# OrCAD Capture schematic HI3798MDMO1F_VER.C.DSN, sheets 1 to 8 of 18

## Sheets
1 SHEET_18: size A3
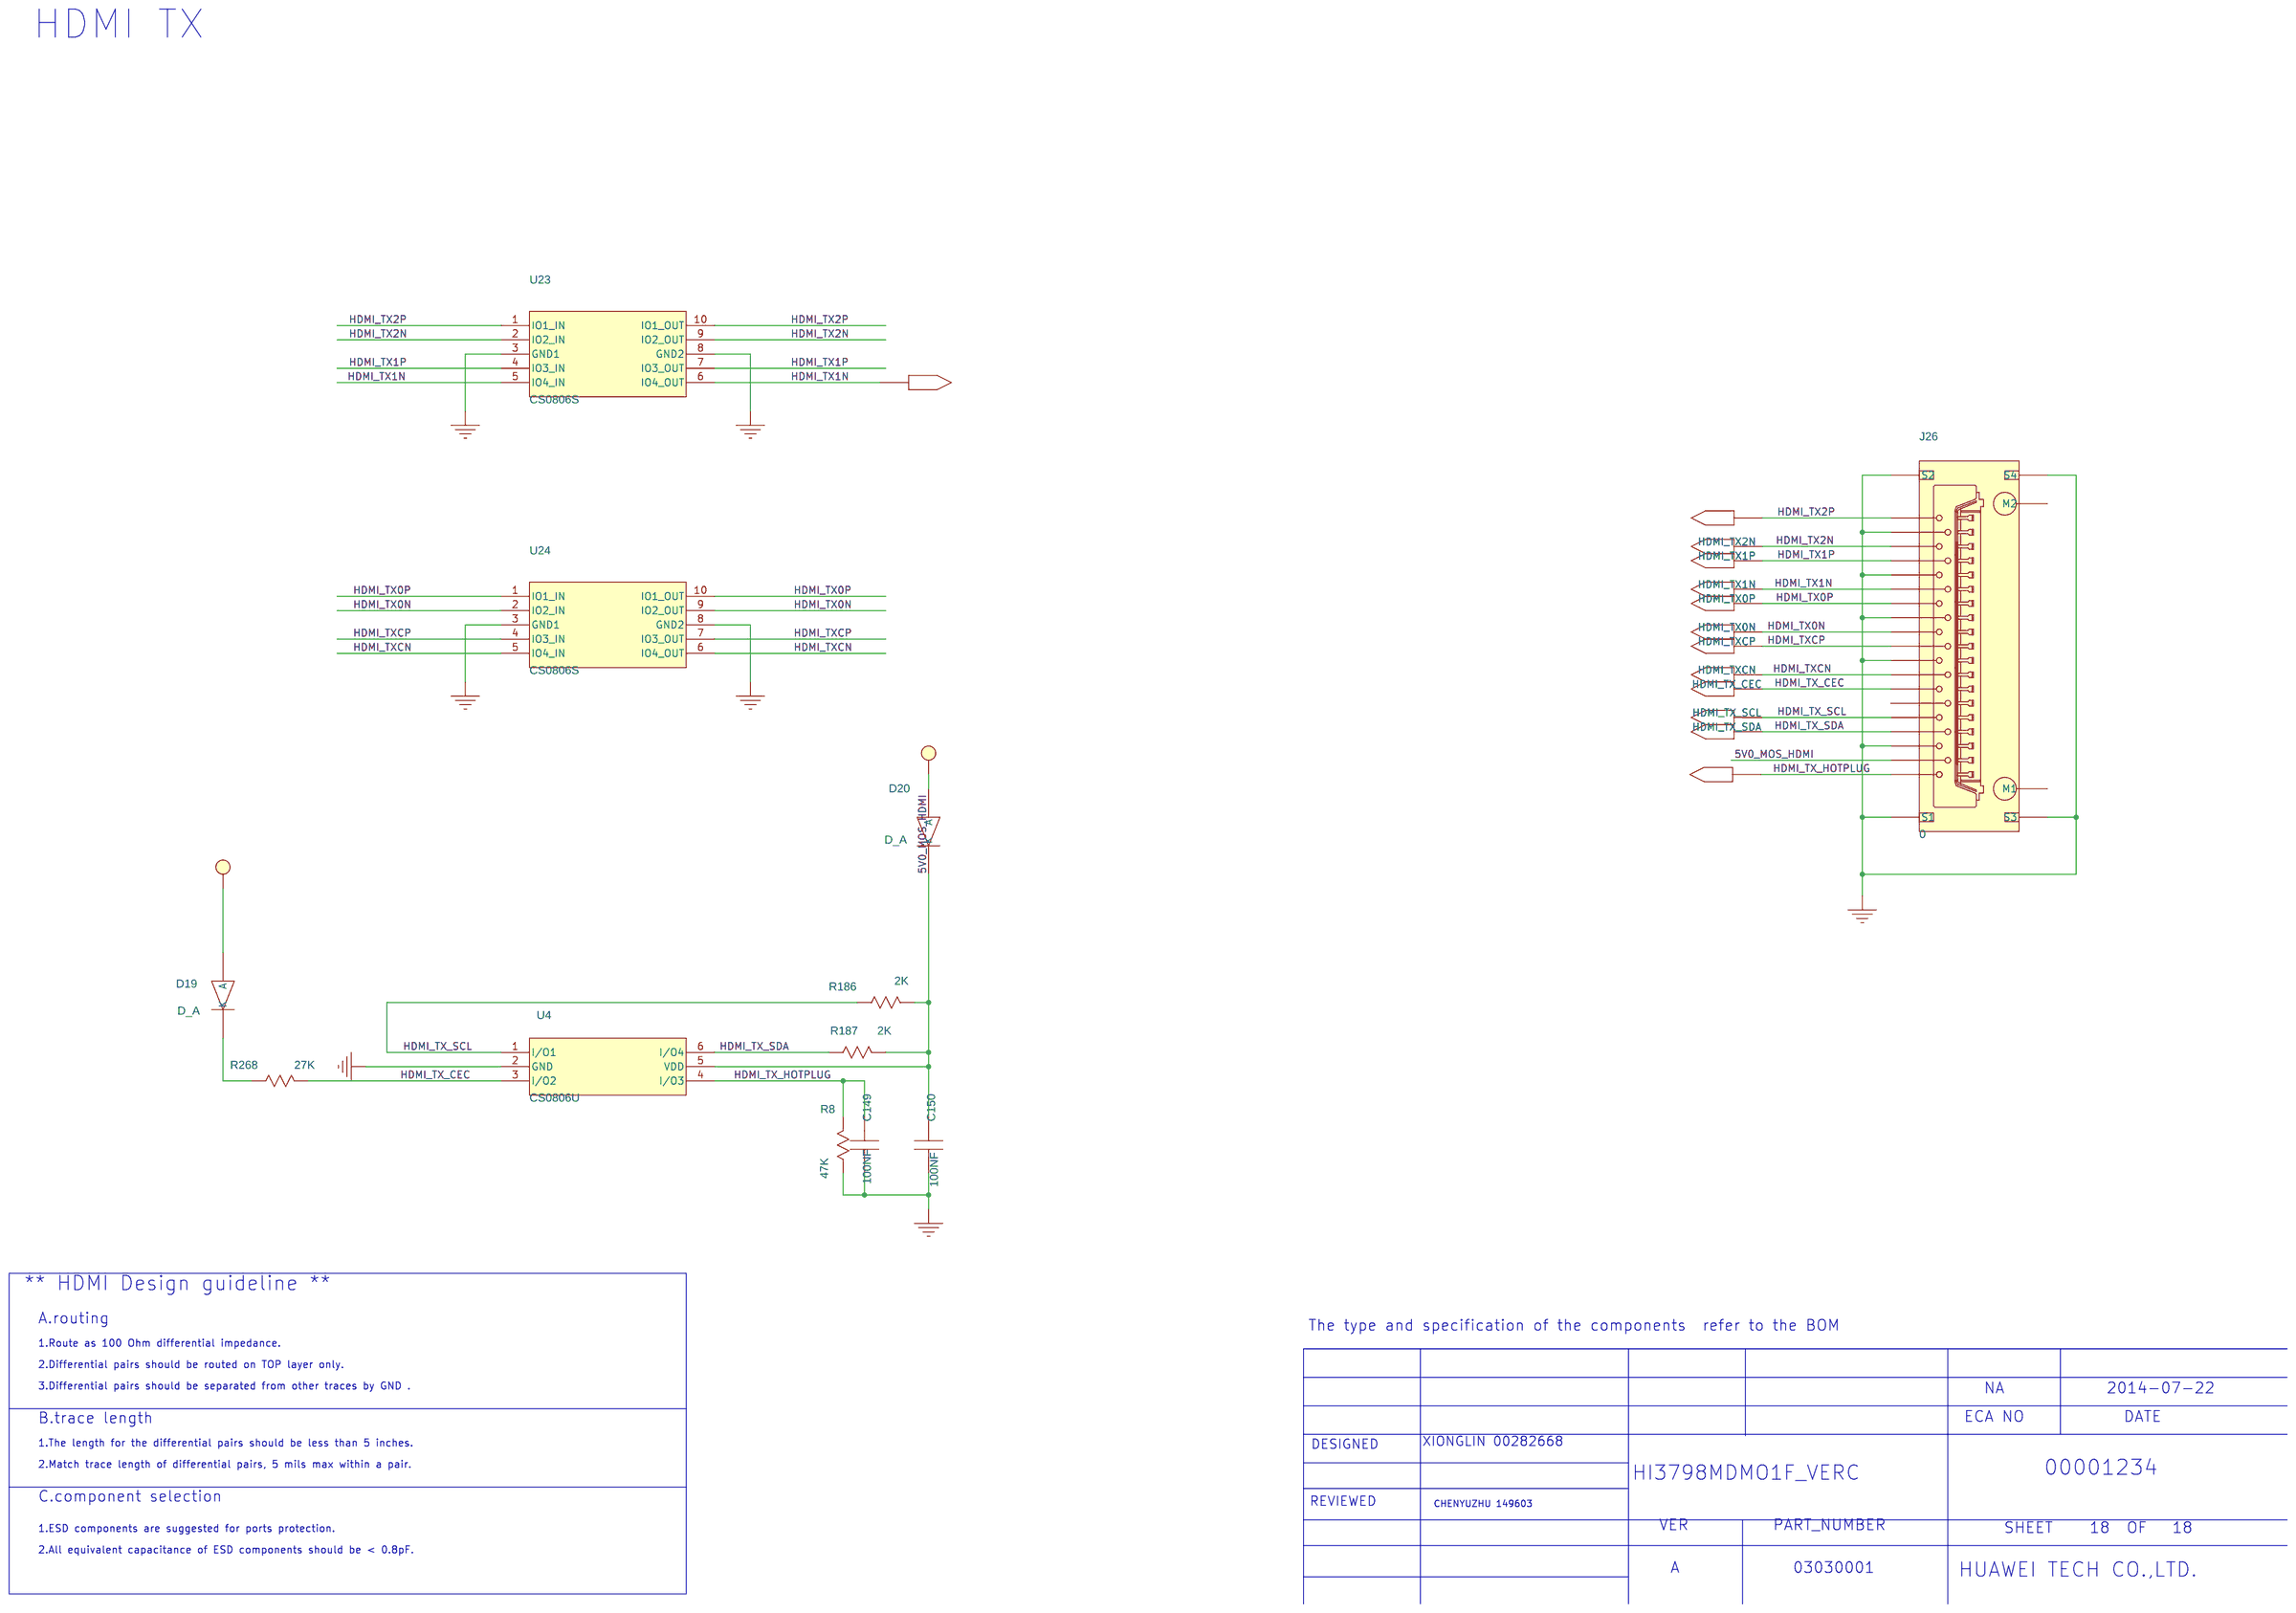
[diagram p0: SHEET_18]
2 SHEET_17: size A3
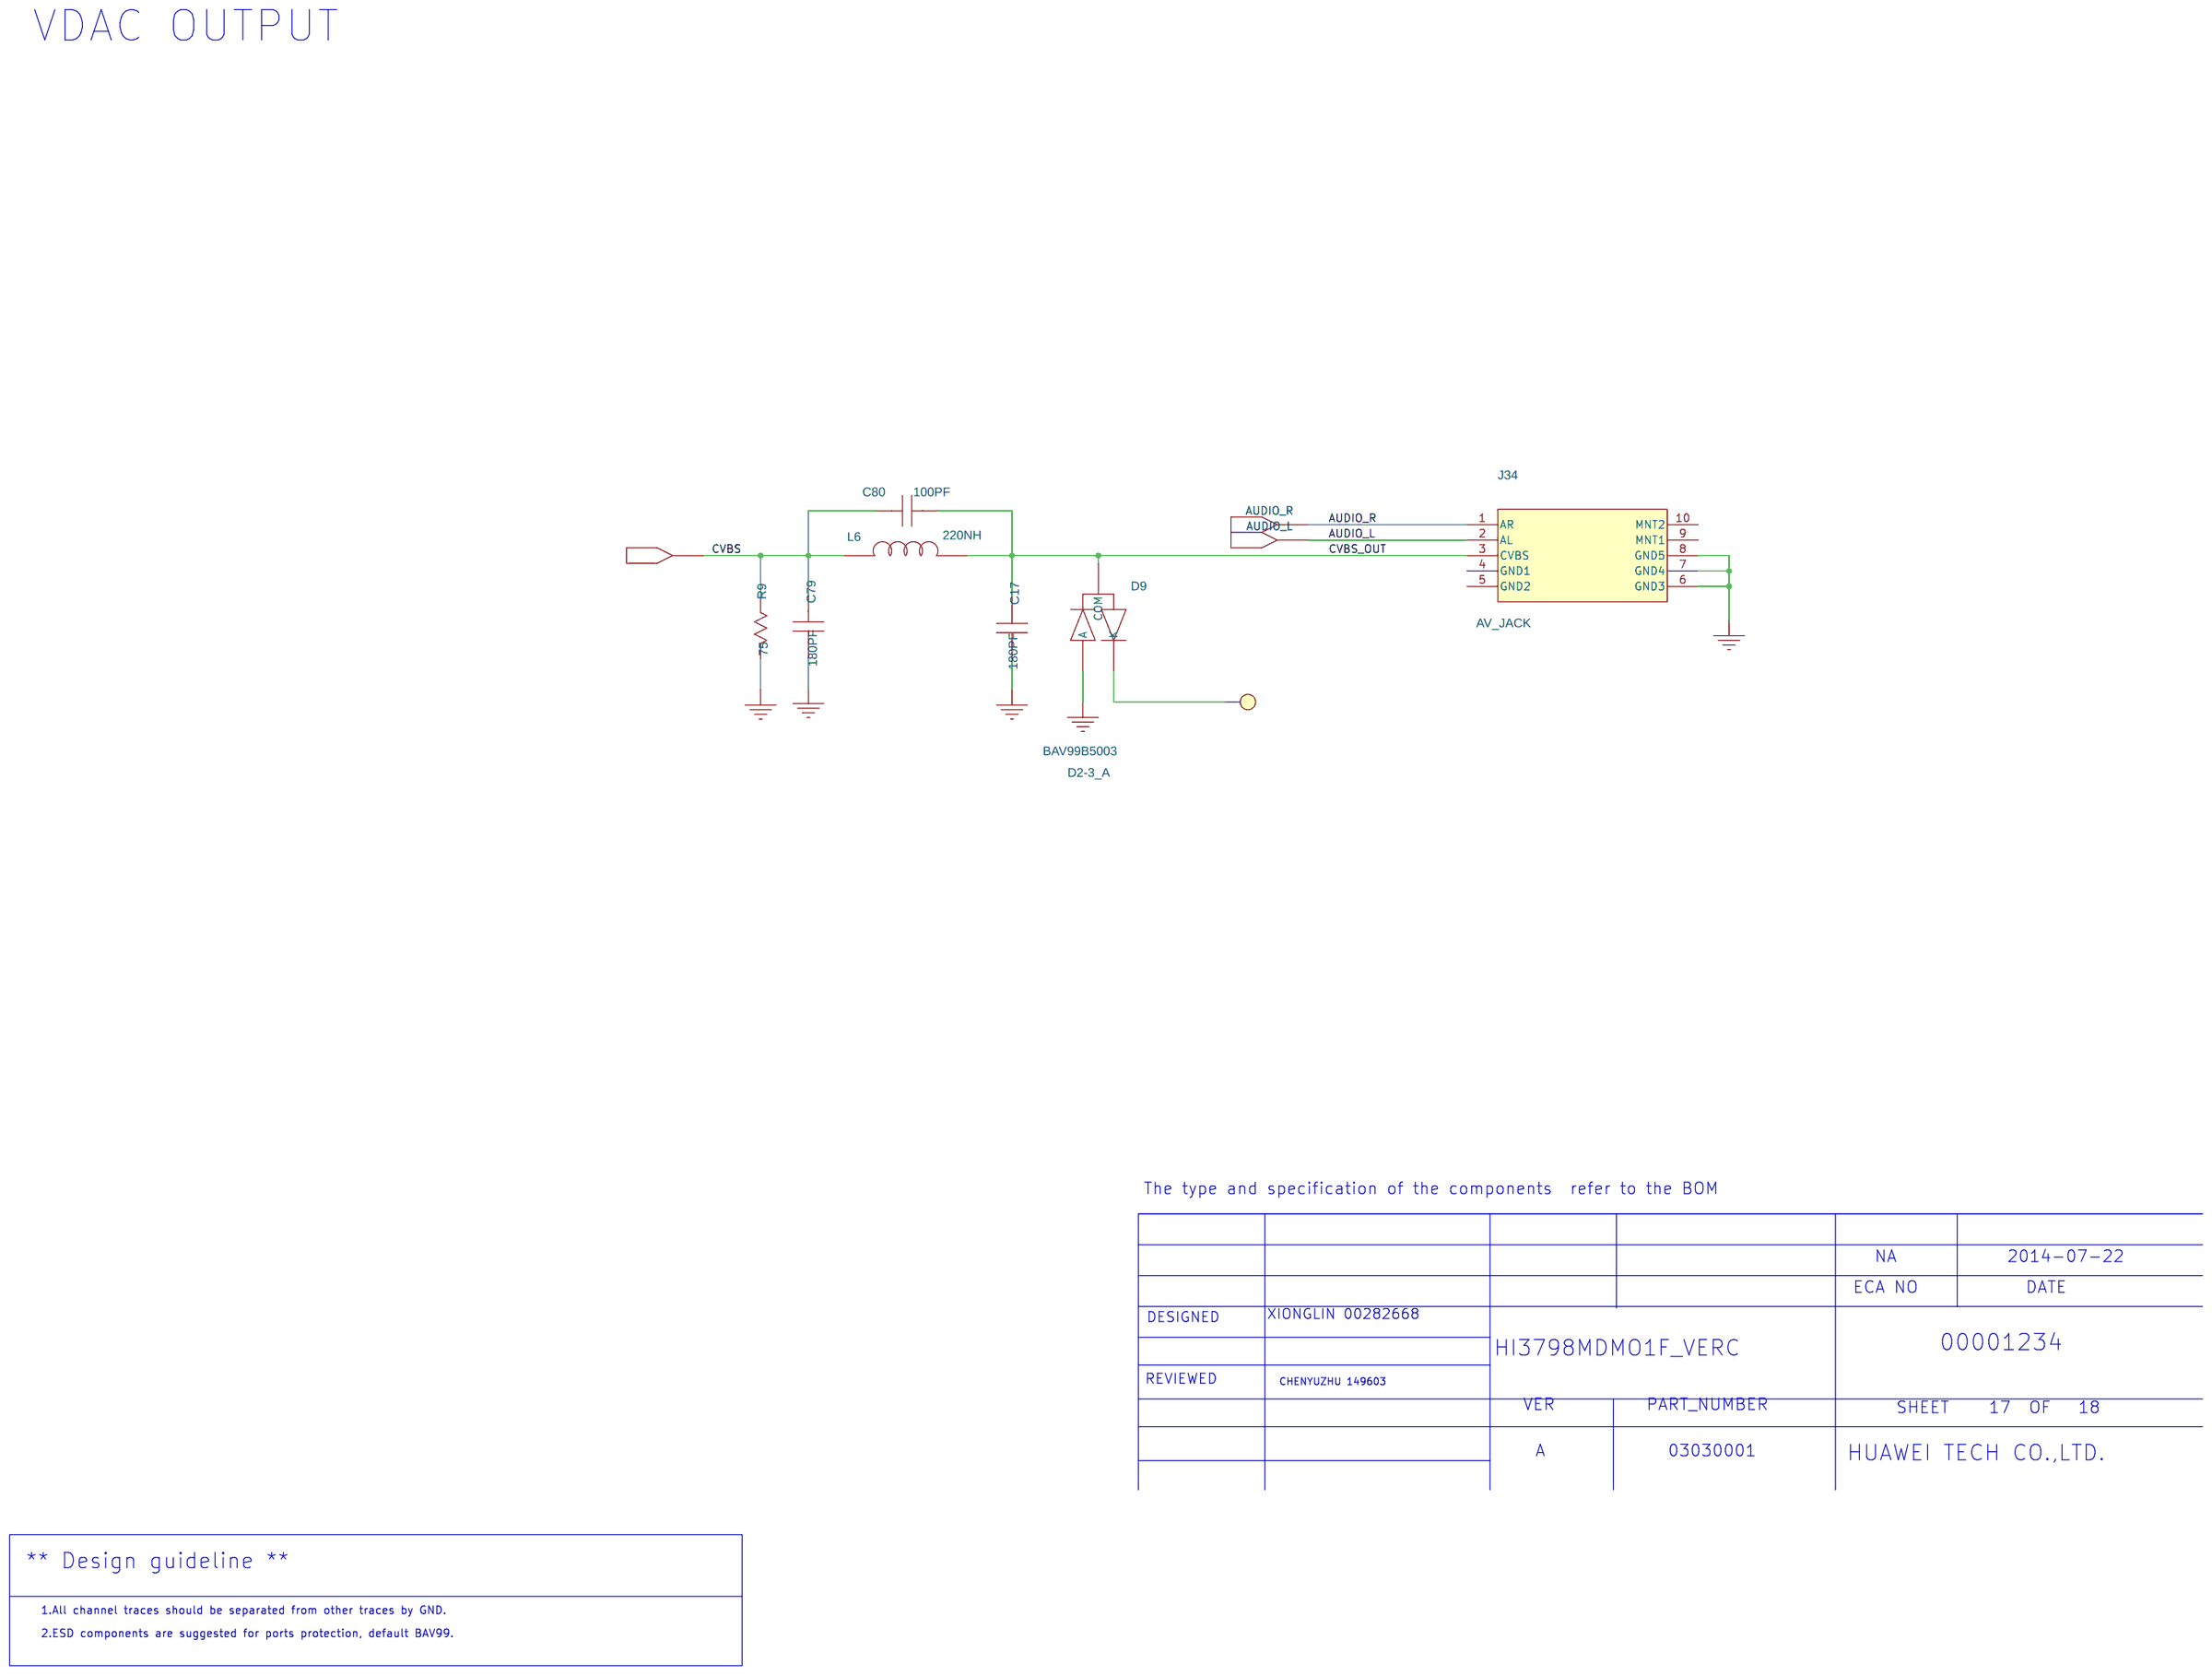
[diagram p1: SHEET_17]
3 SHEET_16: size A3
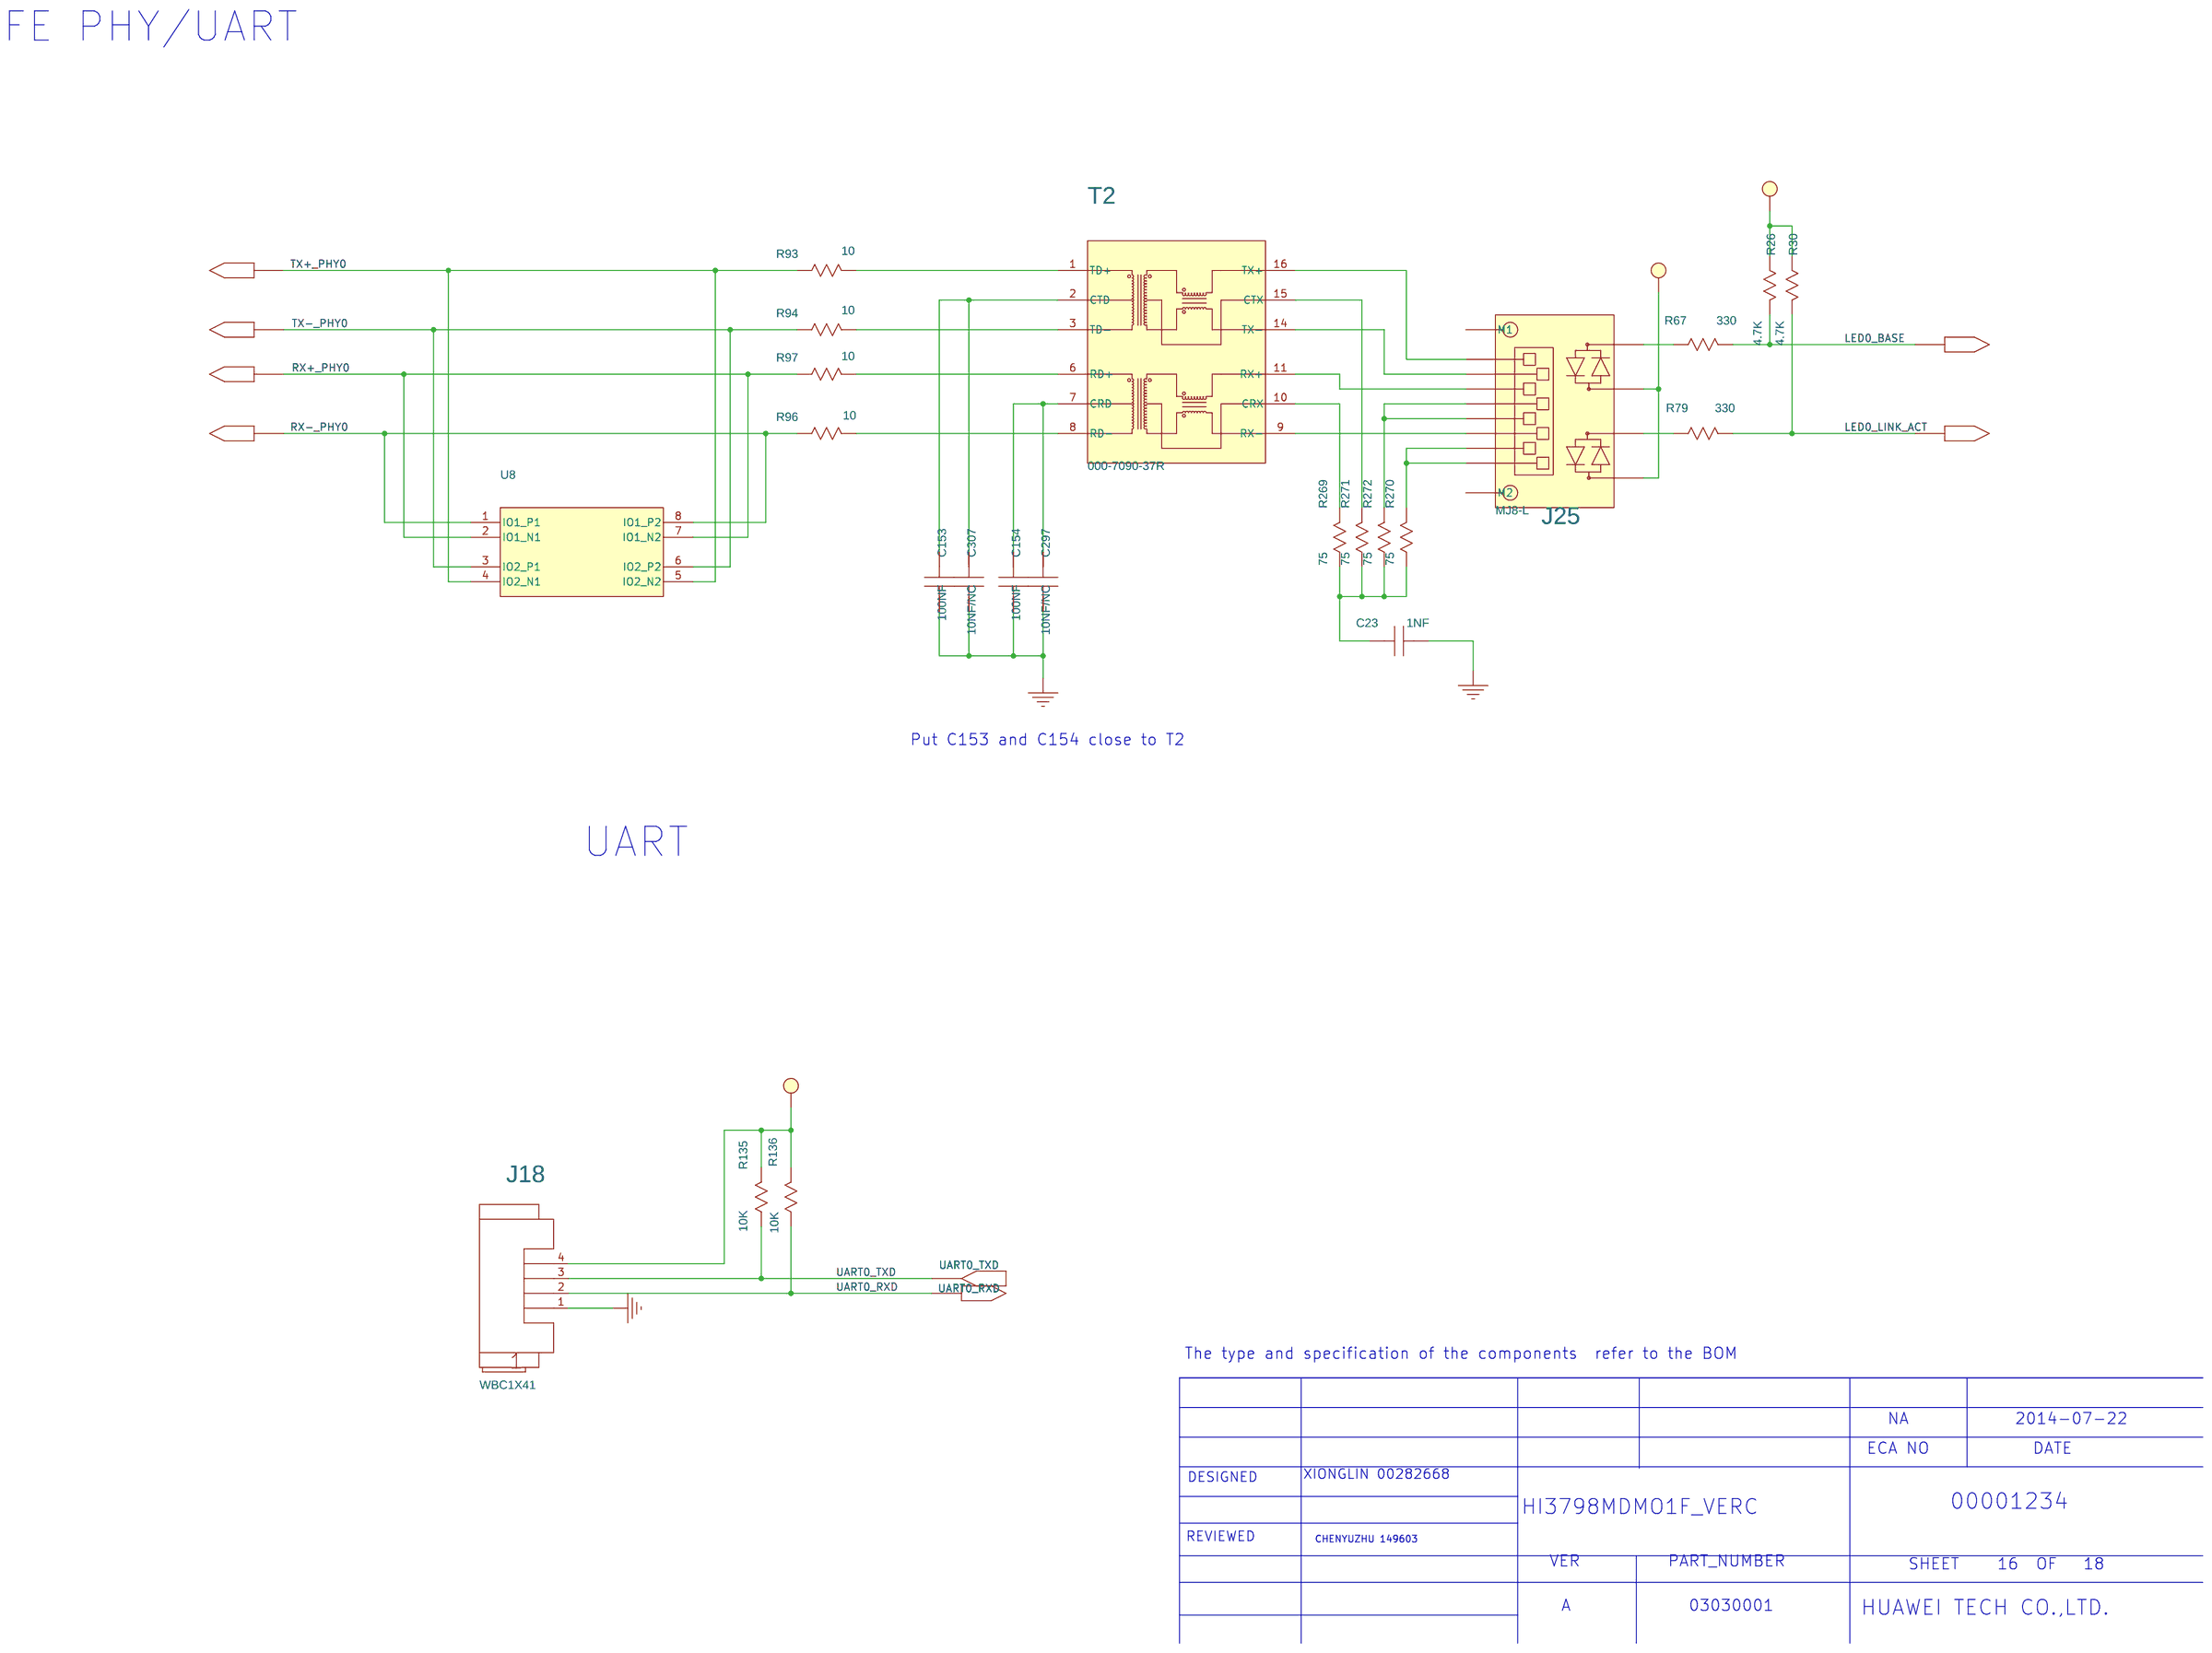
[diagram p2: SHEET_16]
4 SHEET_15: size A3
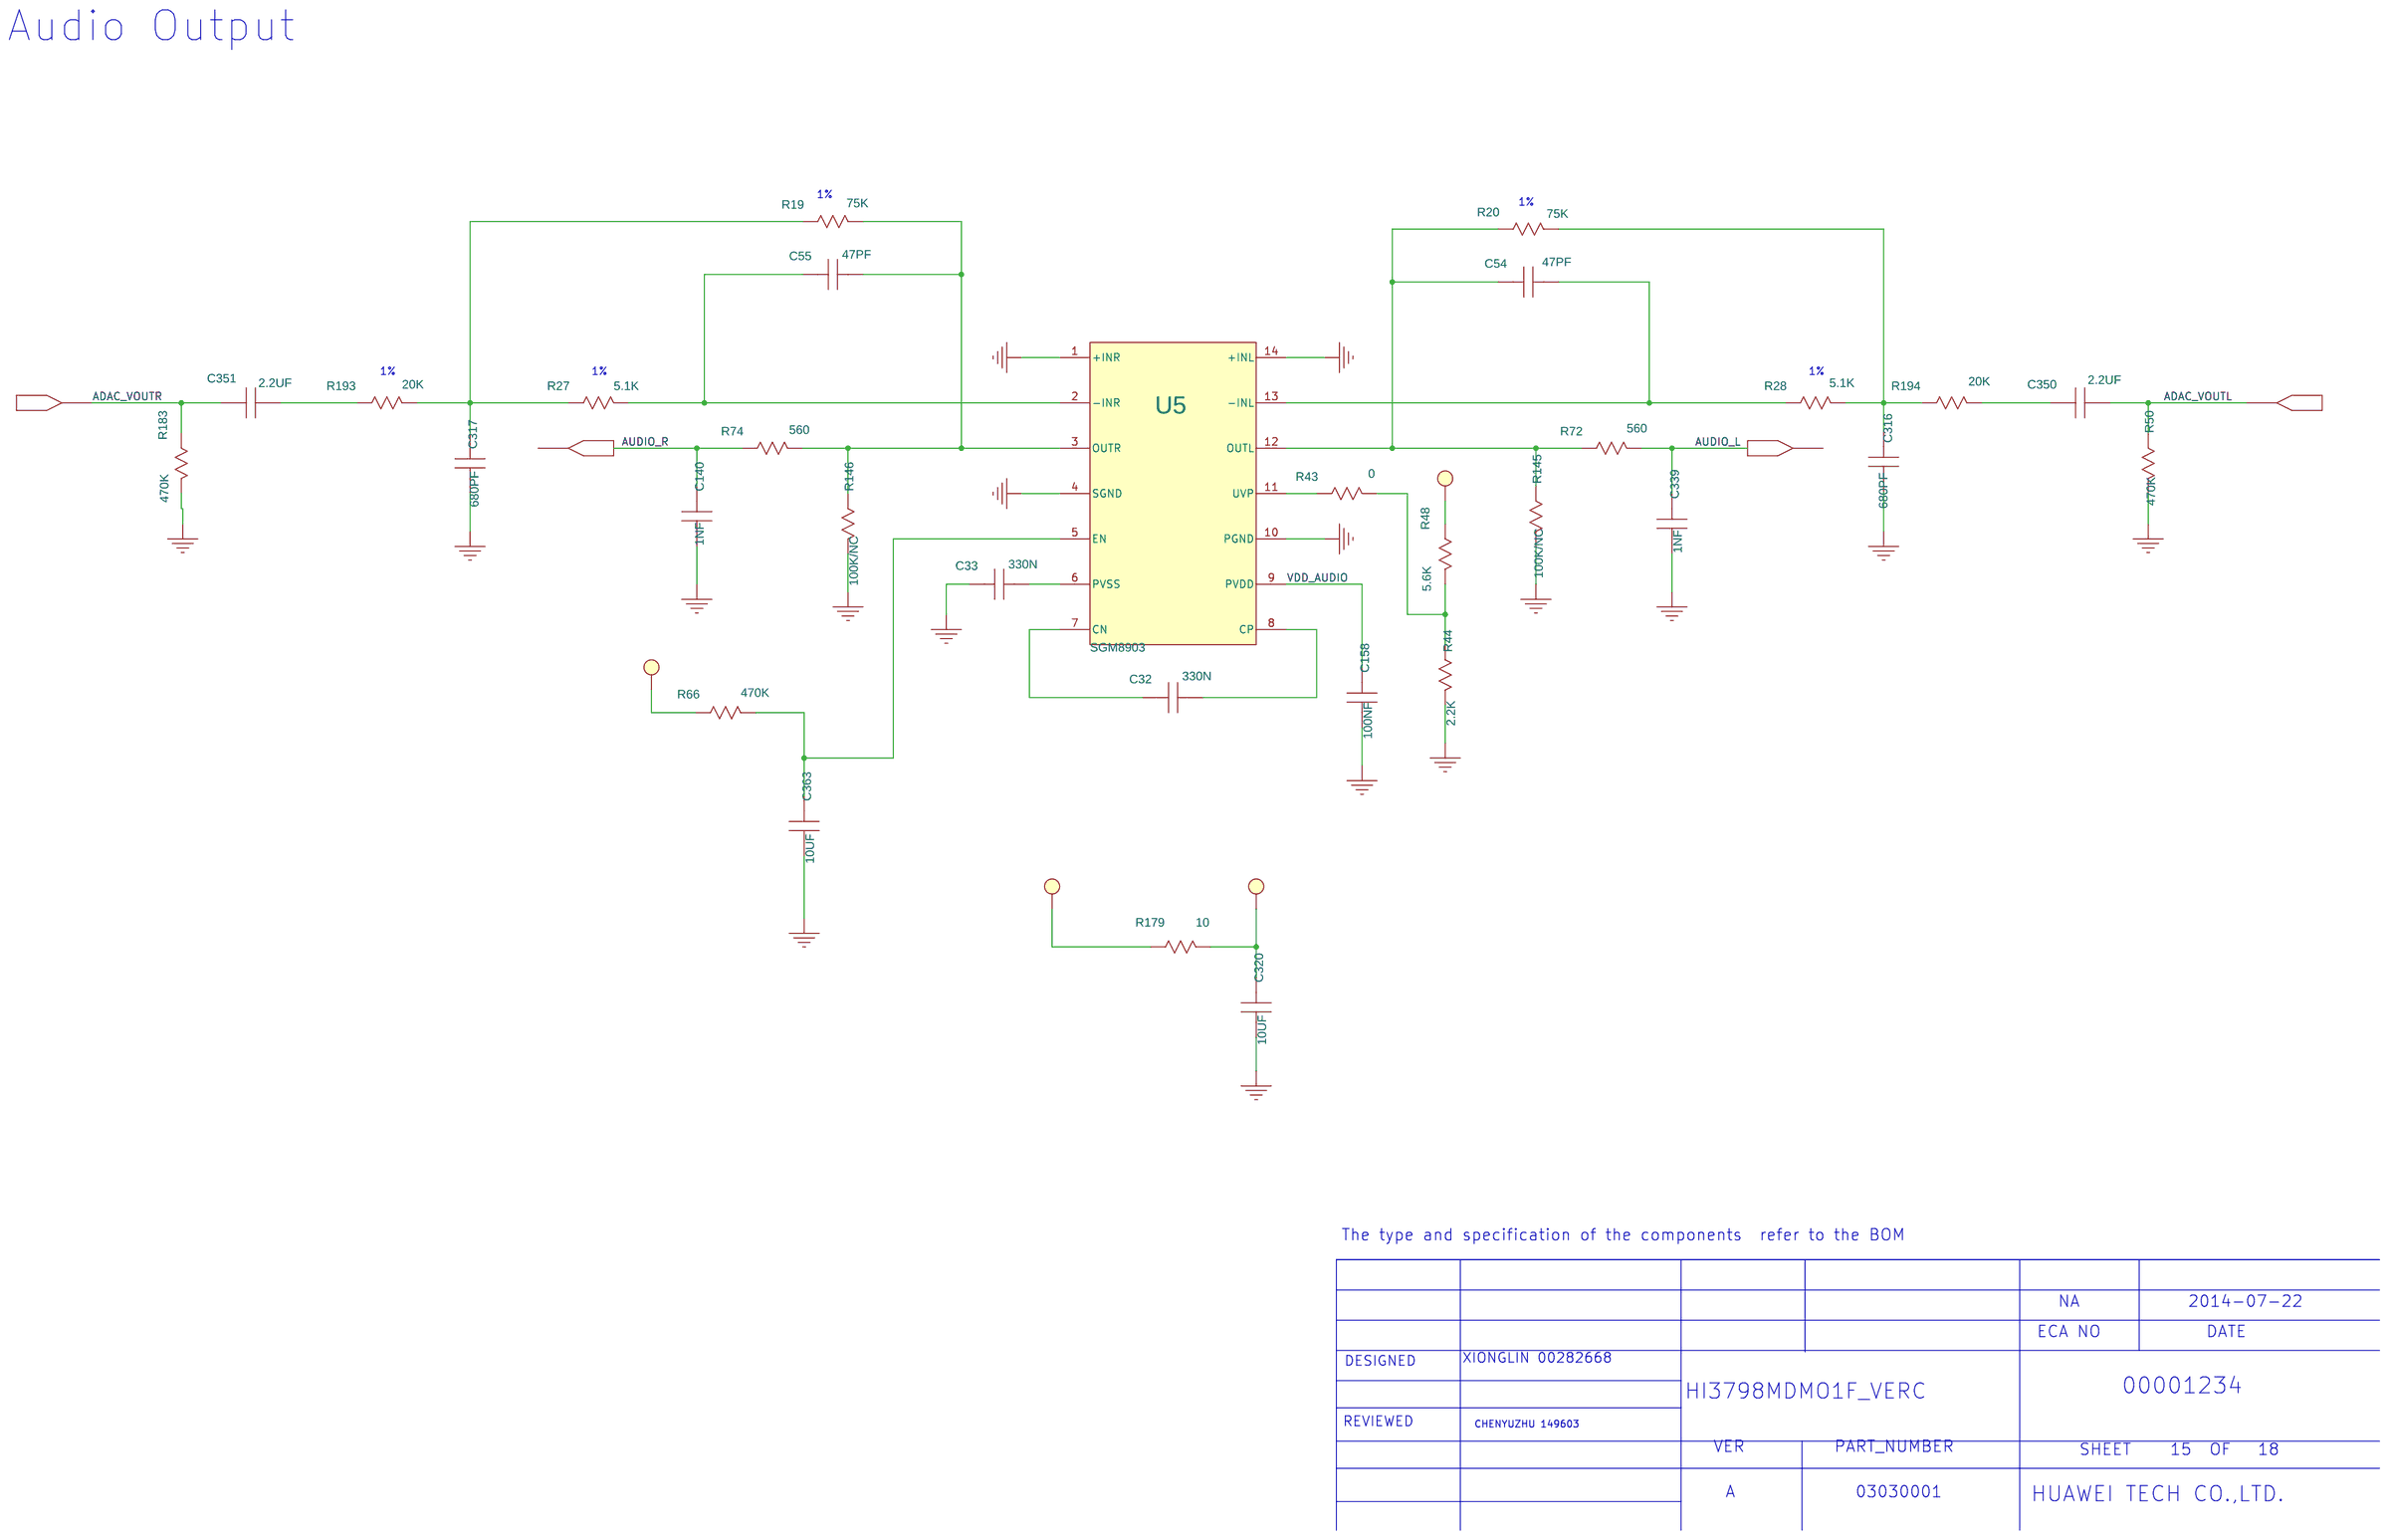
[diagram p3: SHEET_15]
5 SHEET_14: size A3
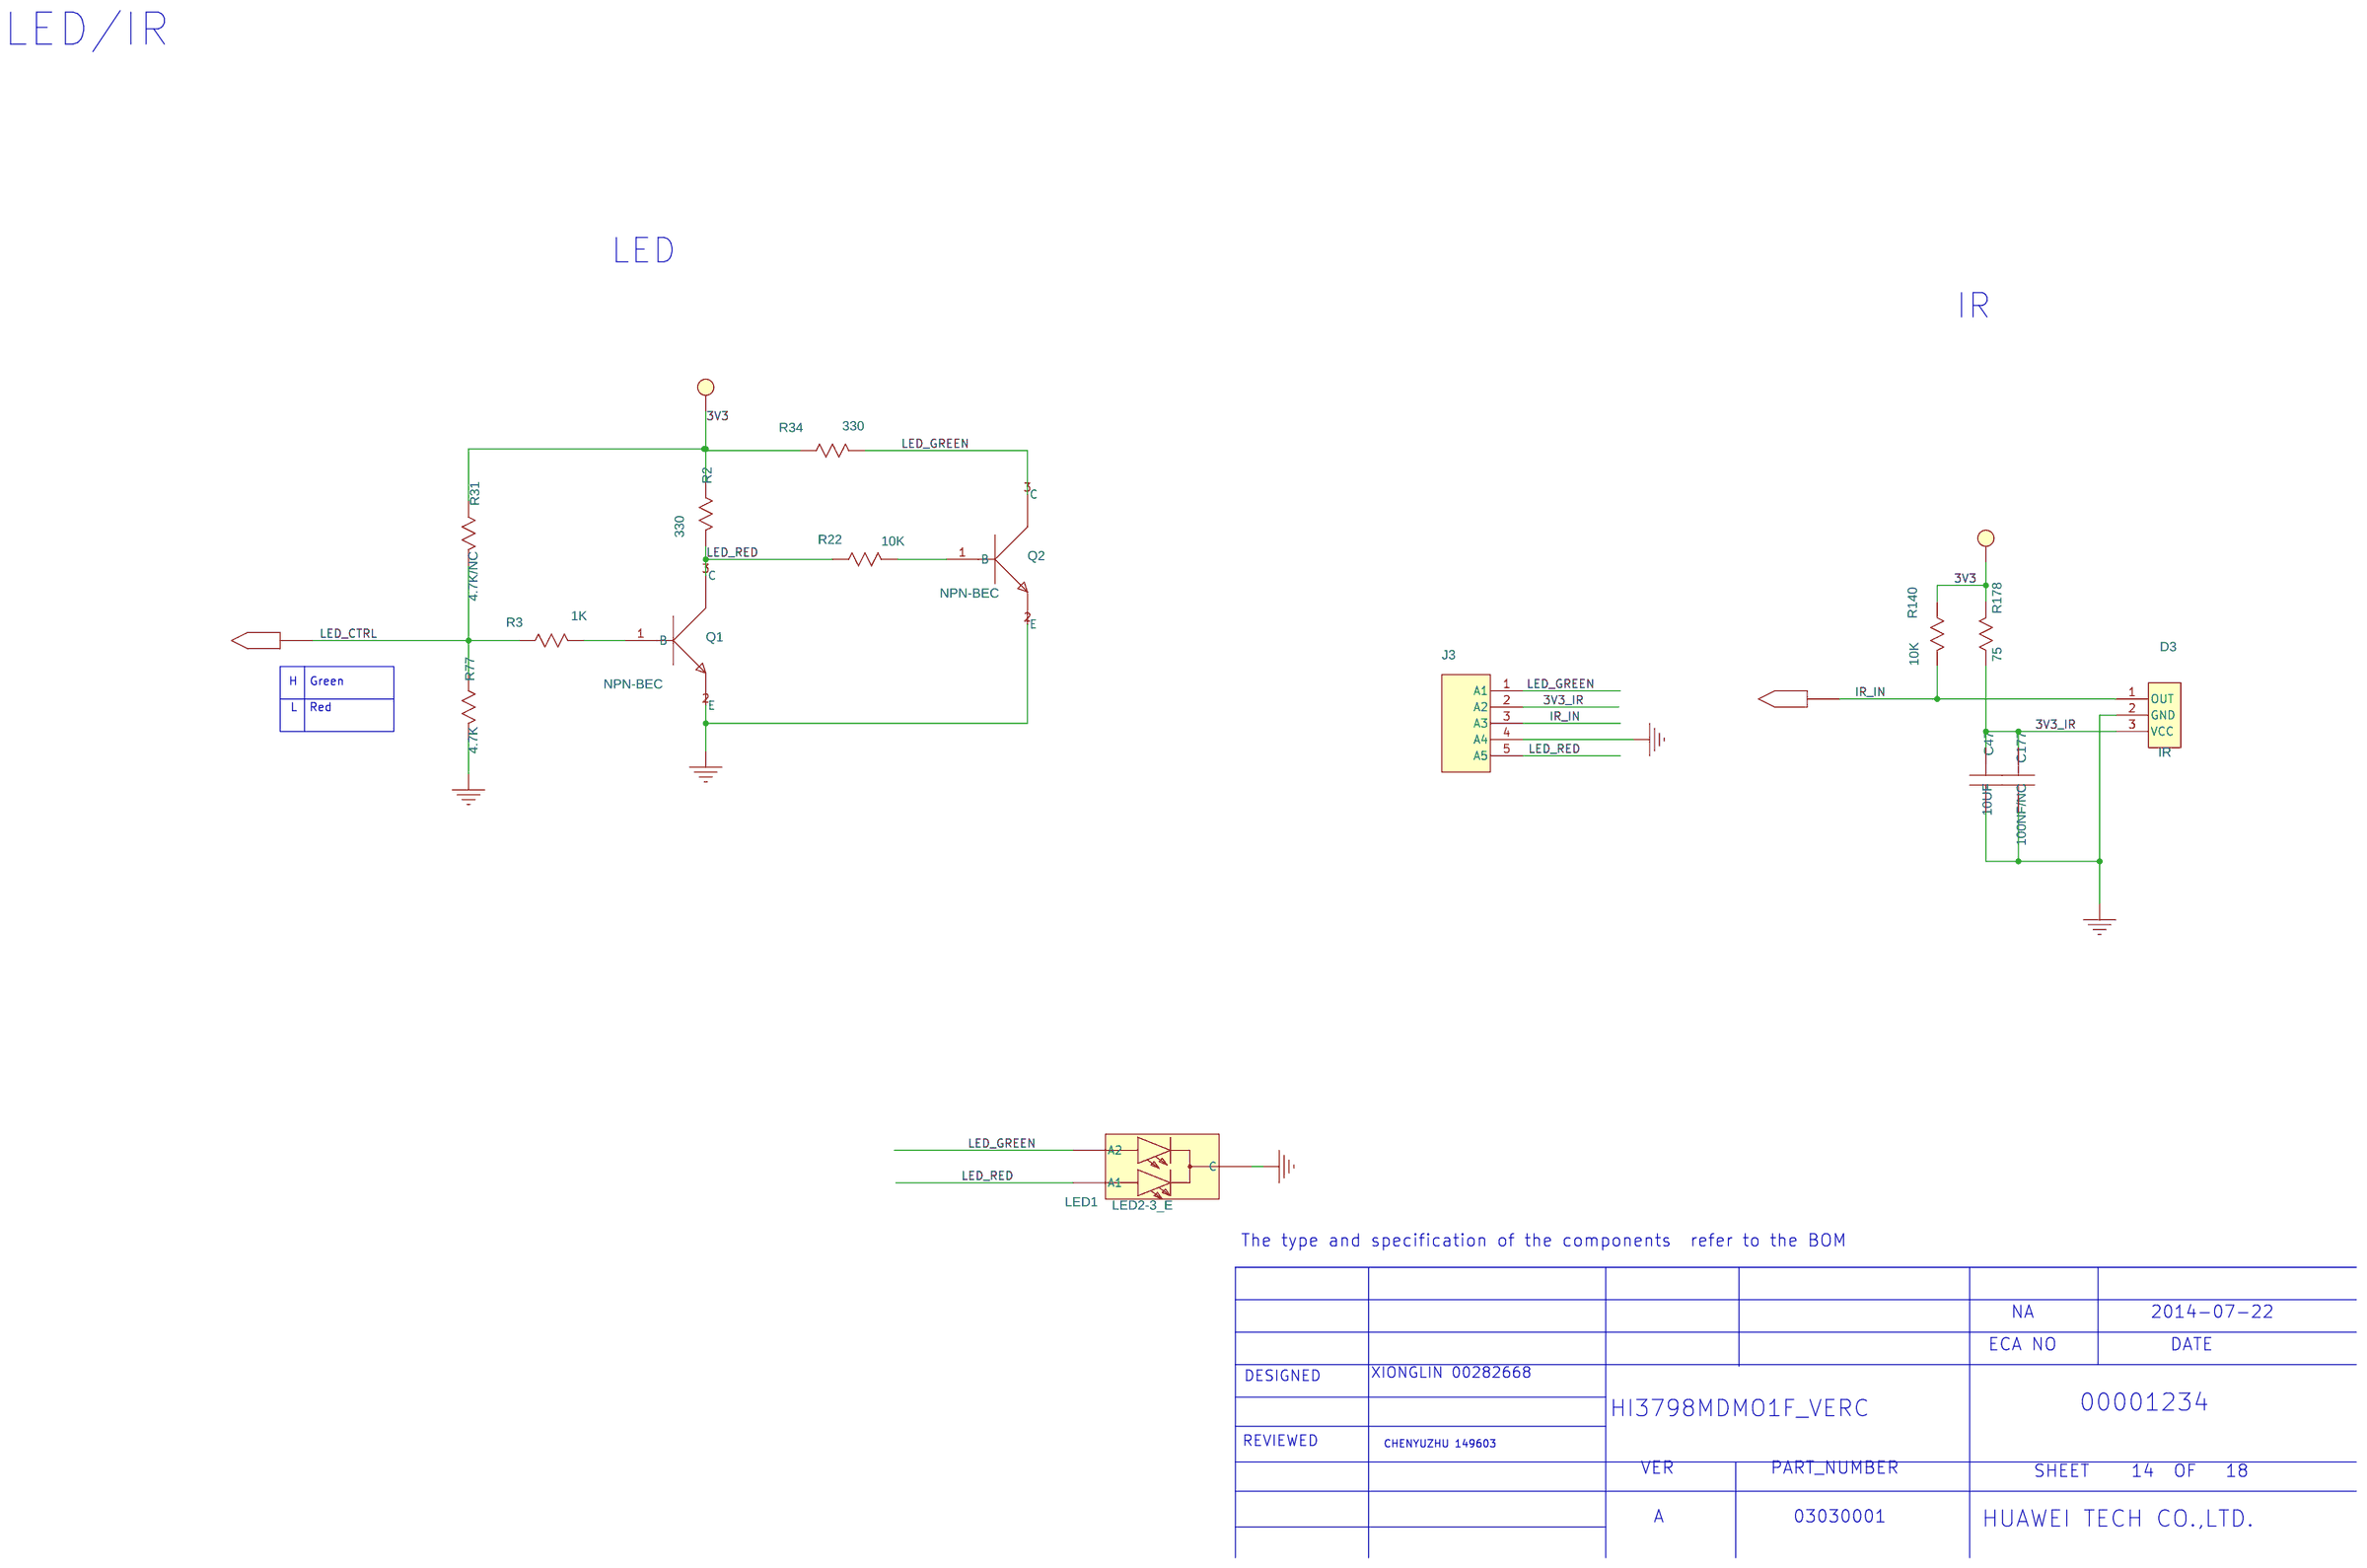
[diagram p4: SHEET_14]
6 SHEET_13: size A3
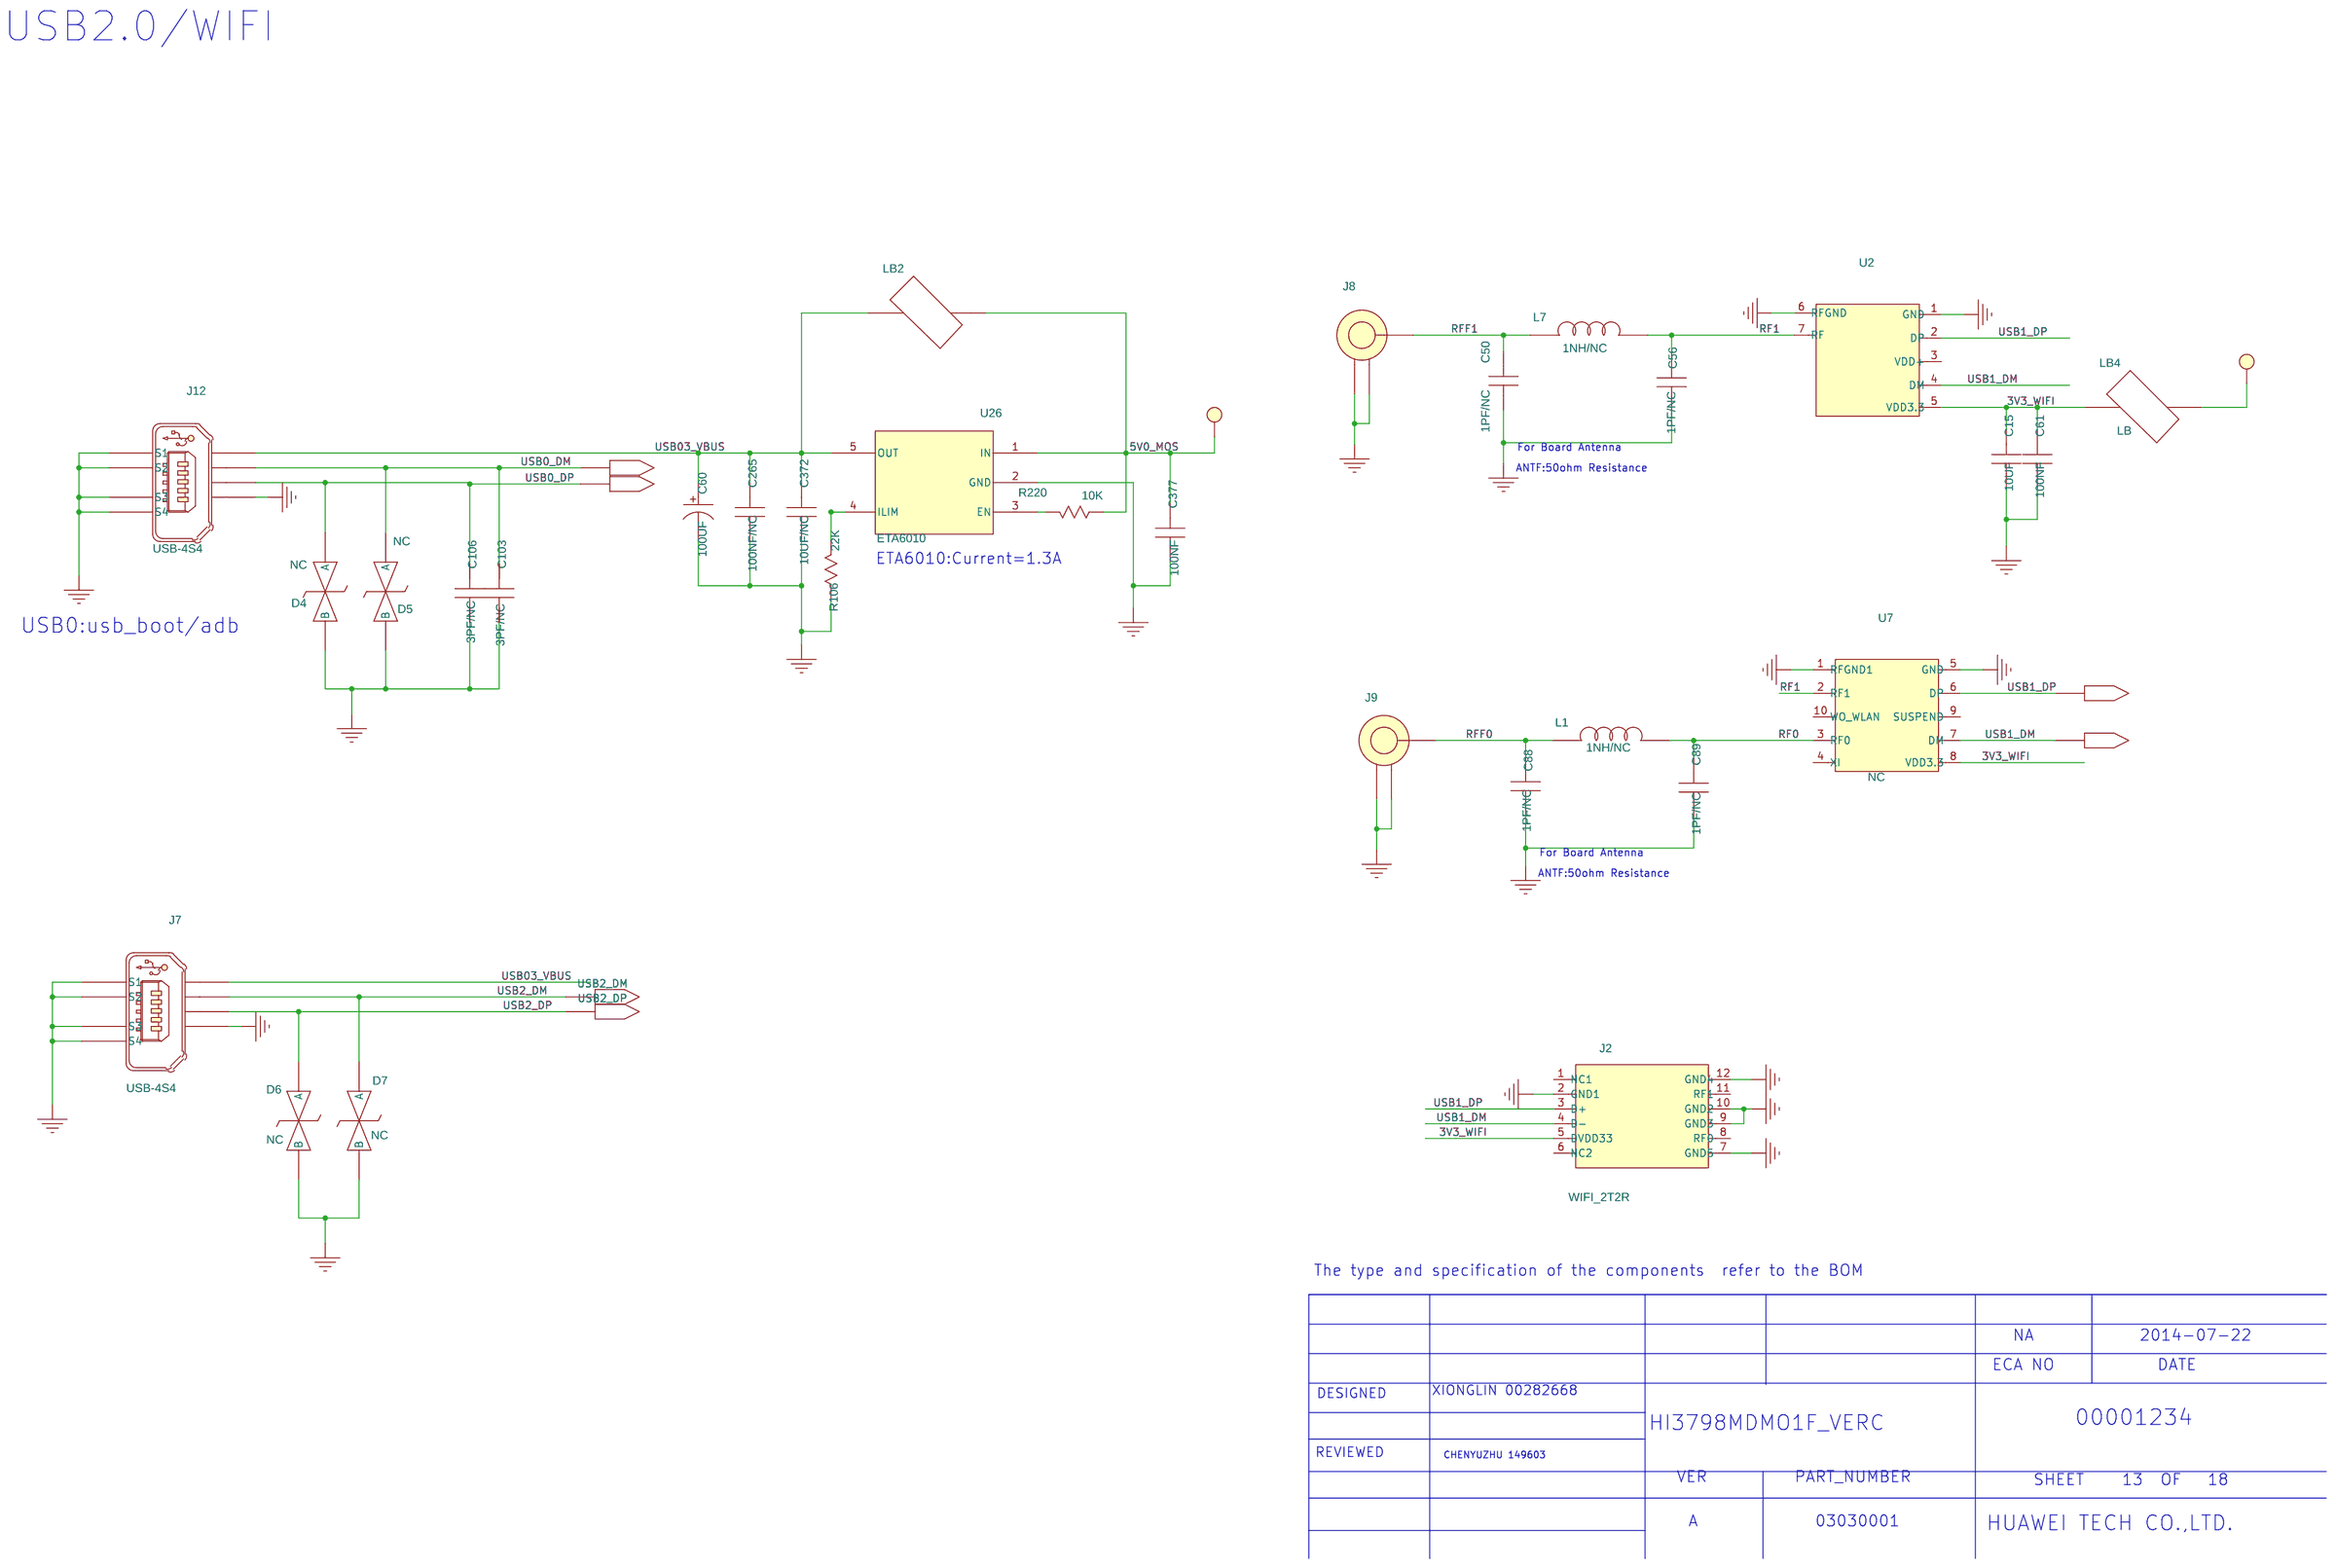
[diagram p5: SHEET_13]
7 SHEET_12: size A3
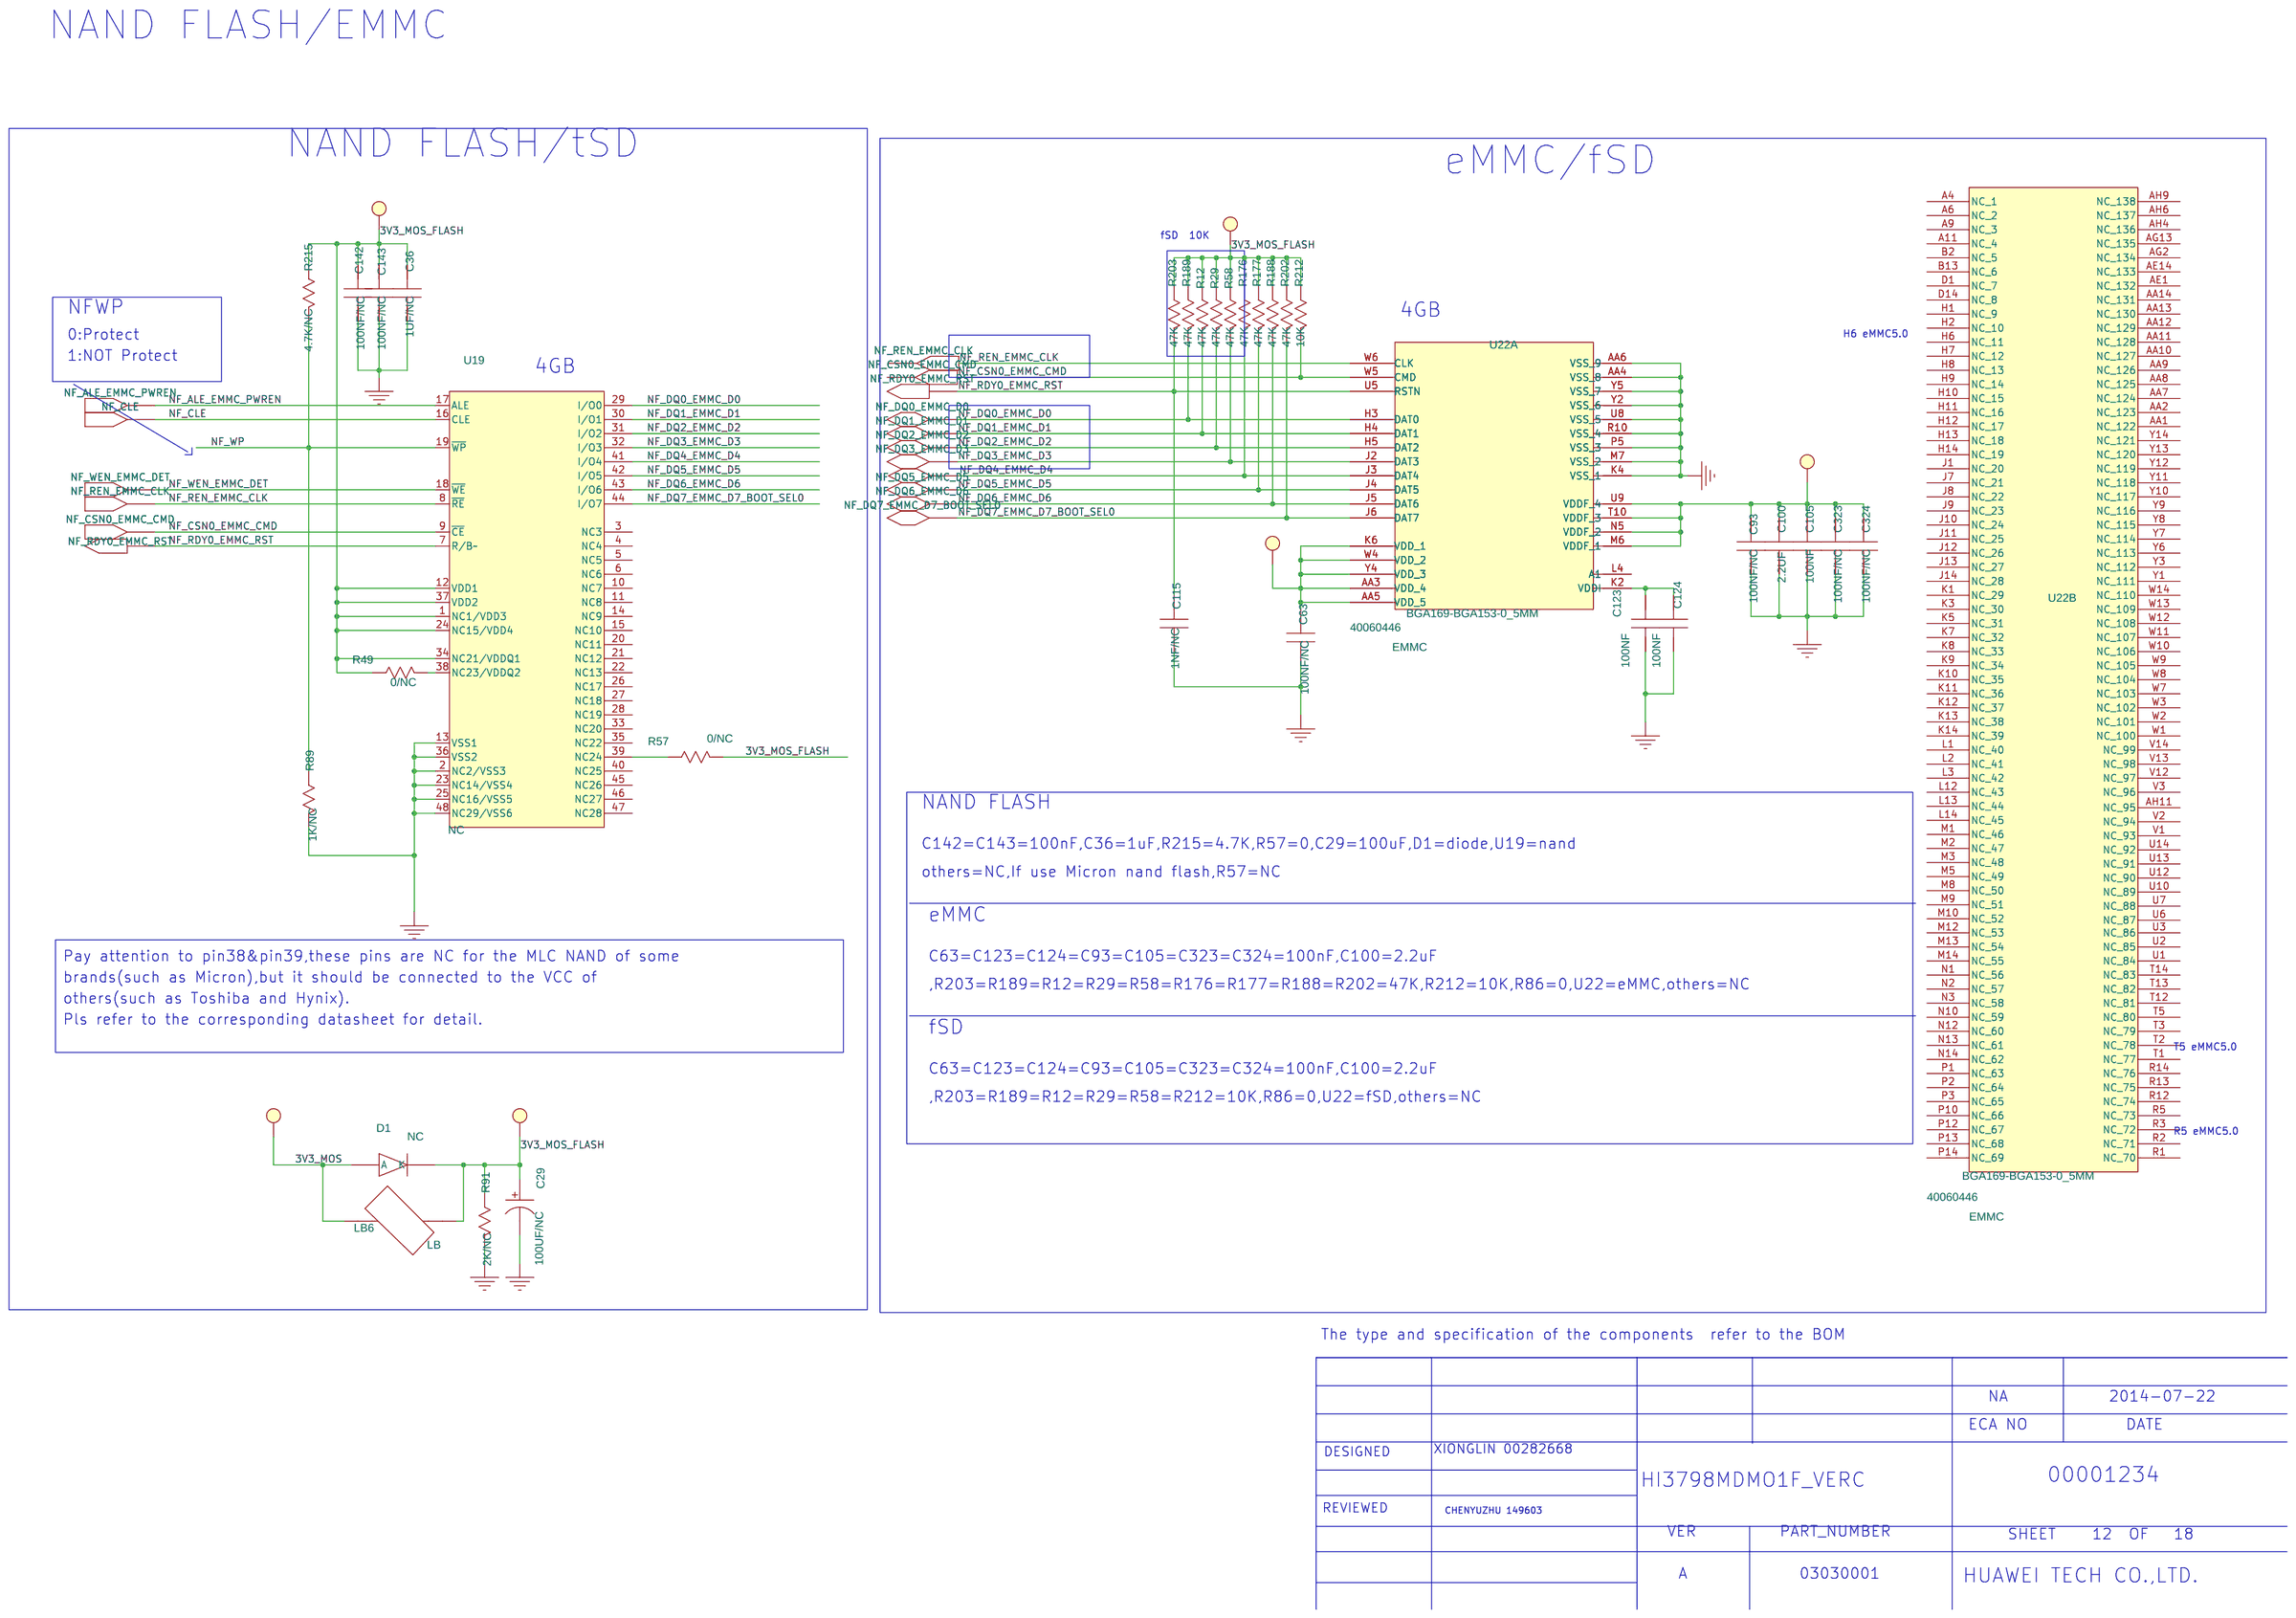
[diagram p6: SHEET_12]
8 SHEET_11: size A3
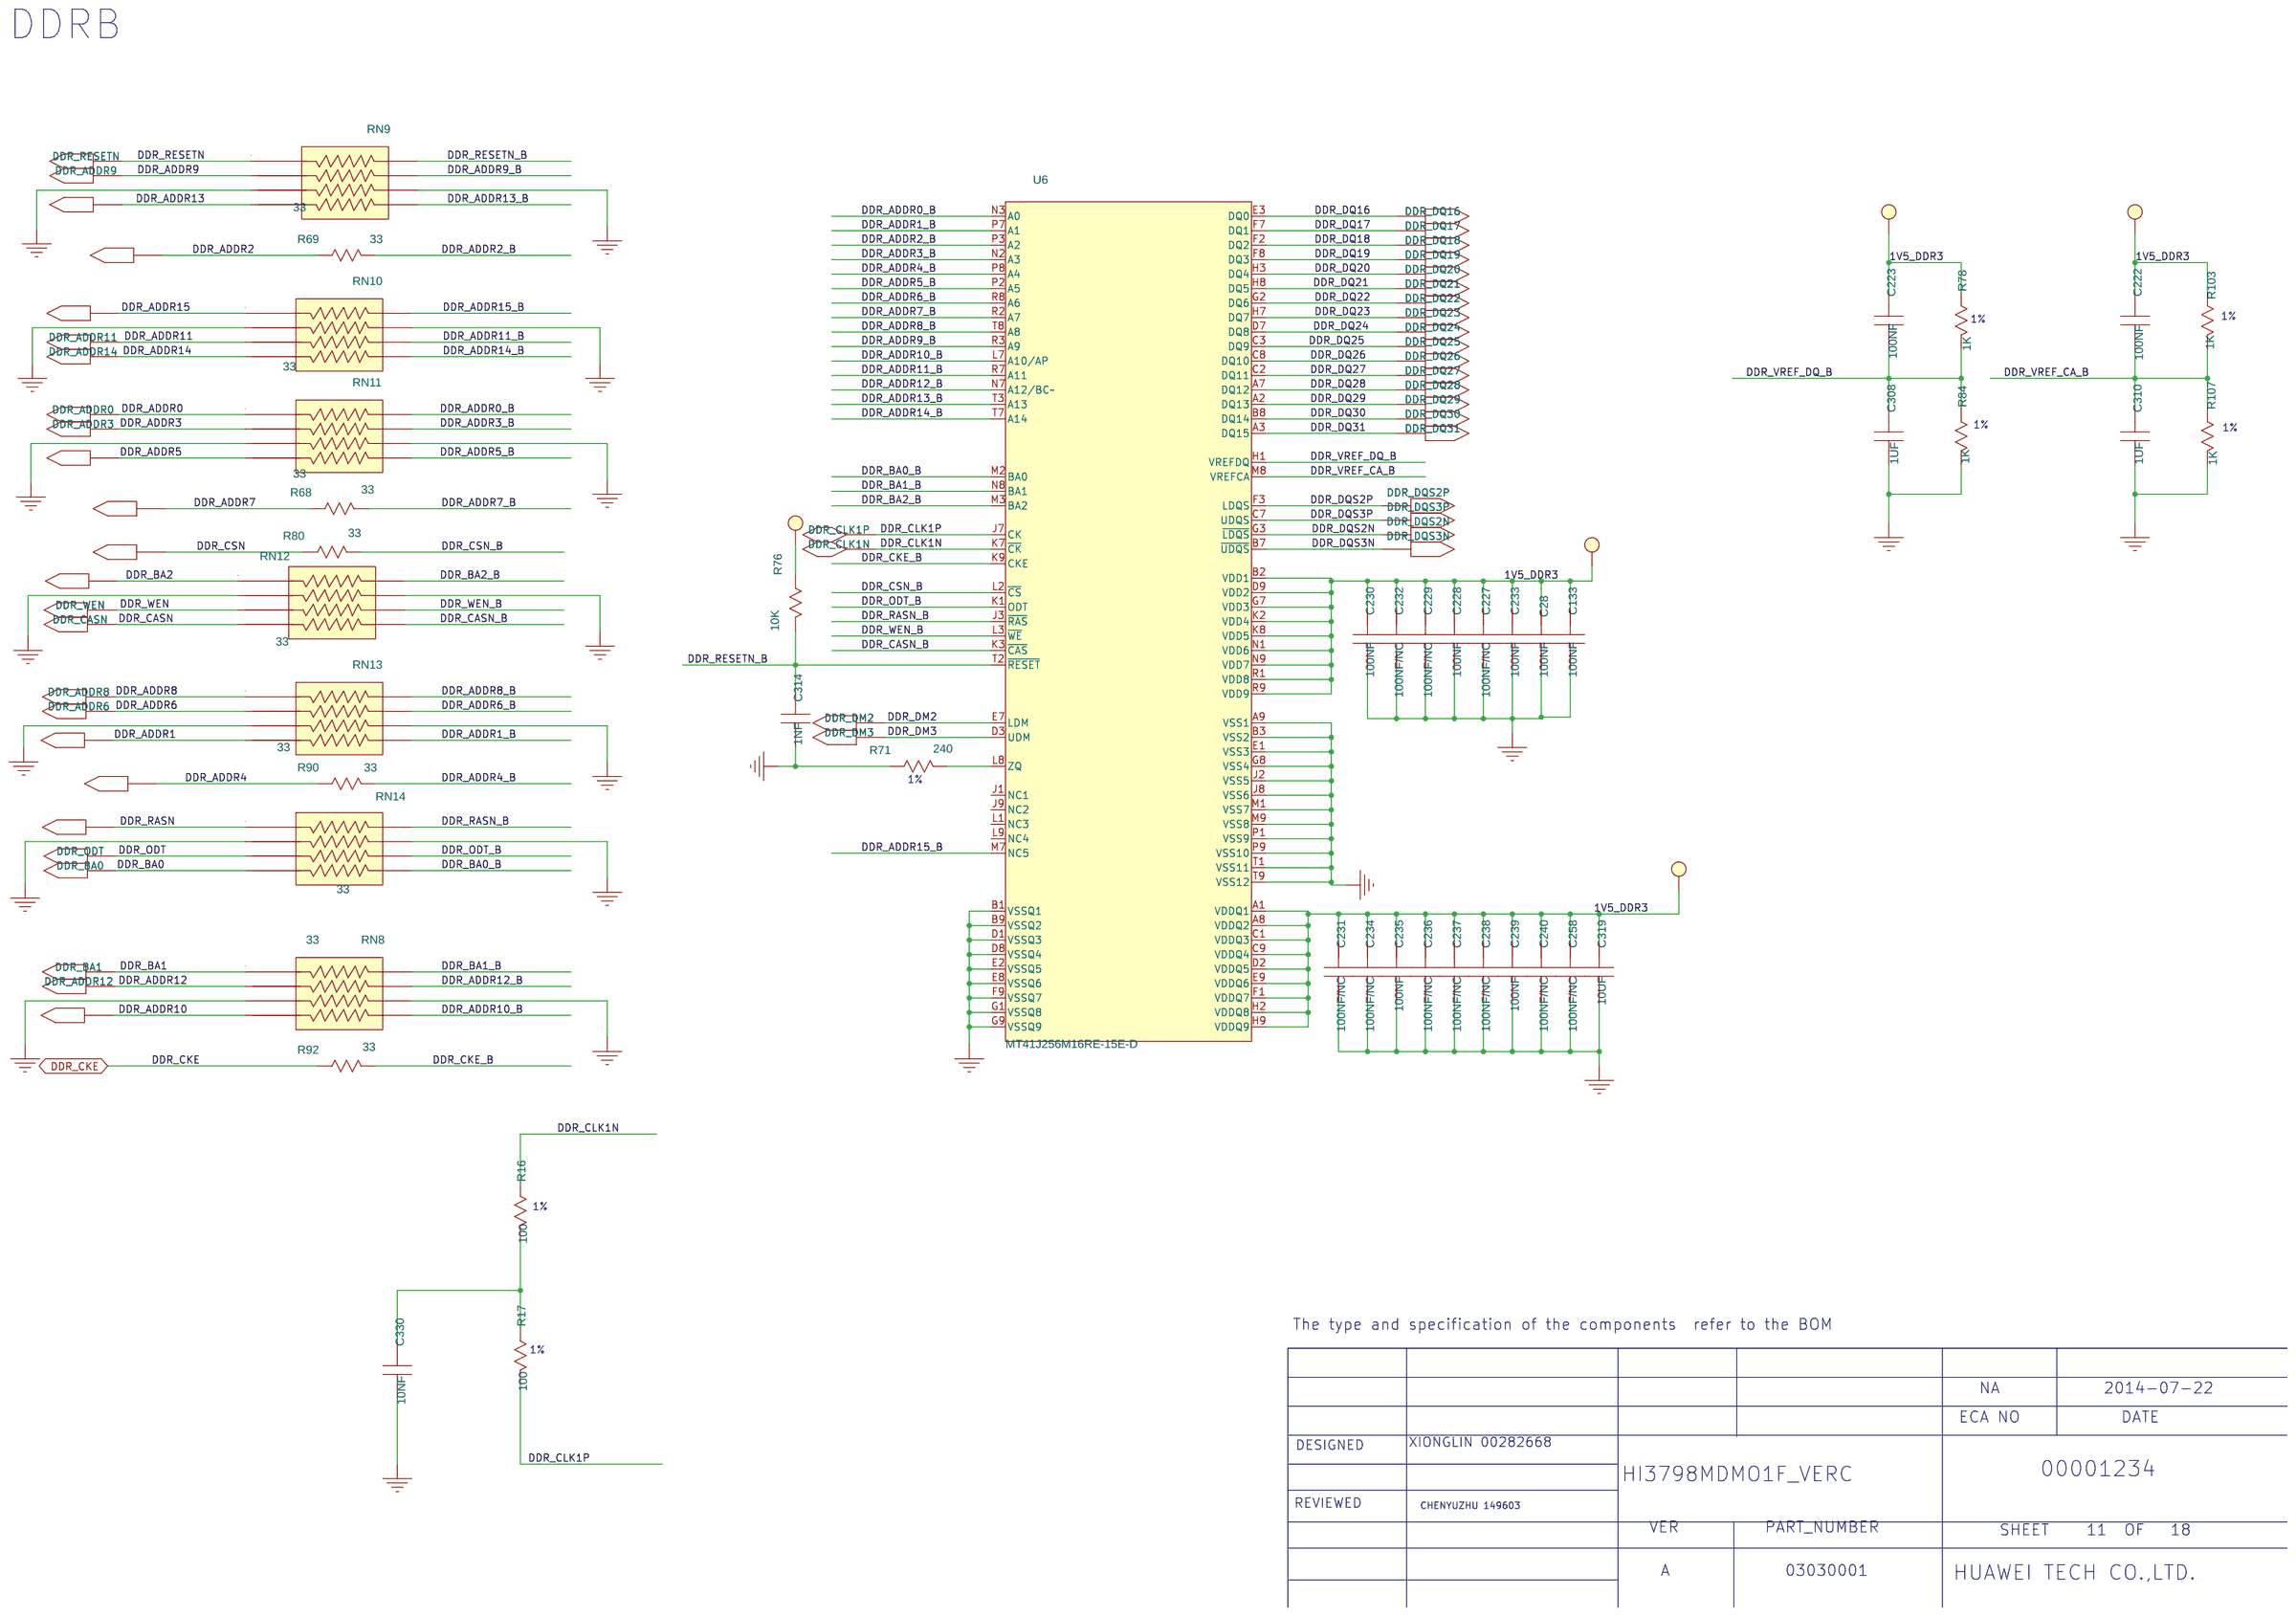
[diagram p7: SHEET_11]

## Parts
sheet SHEET_11
C28  100NF  [SC0402]
C133  100NF  [SC0402]
C222  100NF  [SC0402]
C223  100NF  [SC0402]
C227  100NF/NC  [SC0402]
C228  100NF  [SC0402]
C229  100NF/NC  [SC0402]
C230  100NF  [SC0402]
C231  100NF/NC  [SC0402]
C232  100NF/NC  [SC0402]
C233  100NF  [SC0402]
C234  100NF/NC  [SC0402]
C235  100NF  [SC0402]
C236  100NF/NC  [SC0402]
C237  100NF/NC  [SC0402]
C238  100NF/NC  [SC0402]
C239  100NF  [SC0402]
C240  100NF/NC  [SC0402]
C258  100NF/NC  [SC0402]
C308  1UF  [SC0402]
C310  1UF  [SC0402]
C314  1NF  [SC0402]
C319  10UF  [SC0603]
C330  10NF  [SC0402]
R16  100  [SR0402]
R17  100  [SR0402]
R68  33  [SR0402]
R69  33  [SR0402]
R71  240  [SR0402]
R76  10K  [SR0402]
R78  1K  [SR0402]
R80  33  [SR0402]
R84  1K  [SR0402]
R90  33  [SR0402]
R92  33  [SR0402]
R103  1K  [SR0402]
R107  1K  [SR0402]
RN8  33  [SRN8-0804]
RN9  33  [SRN8-0804]
RN10  33  [SRN8-0804]
RN11  33  [SRN8-0804]
RN12  33  [SRN8-0804]
RN13  33  [SRN8-0804]
RN14  33  [SRN8-0804]
U6  MT41J256M16RE-15E-D  [BGA96-32-1609I]
sheet SHEET_12
C29  100UF/NC  [SAC6666]
C36  1UF/NC  [SC0603]
C63  100NF/NC  [SC0402]
C93  100NF/NC  [SC0402]
C100  2.2UF  [SC0603]
C105  100NF  [SC0402]
C115  1NF/NC  [SC0402]
C123  100NF  [SC0402]
C124  100NF  [SC0402]
C142  100NF/NC  [SC0402]
C143  100NF/NC  [SC0402]
C323  100NF/NC  [SC0402]
C324  100NF/NC  [SC0402]
D1  NC  [HSOD323A]
LB6  LB  [SL0402]
R12  47K  [SR0402]
R29  47K  [SR0402]
R49  0/NC  [SR0402]
R57  0/NC  [SR0402]
R58  47K  [SR0402]
R89  1K/NC  [SR0402]
R91  2K/NC  [SR0603]
R176  47K  [SR0402]
R177  47K  [SR0402]
R188  47K  [SR0402]
R189  47K  [SR0402]
R202  47K  [SR0402]
R203  47K  [SR0402]
R212  10K  [SR0402]
R215  4.7K/NC  [SR0402]
U19  NC  [SOP48-20-720B]
U22  EMMC  [BGA169-BGA153-0_5MM]  (sections A,B)
sheet SHEET_13
C15  10UF  [SC0603]
C50  1PF/NC  [SC0402]
C56  1PF/NC  [SC0402]
C60  100UF  [SAC6666]
C61  100NF  [SC0603]
C88  1PF/NC  [SC0402]
C89  1PF/NC  [SC0402]
C103  3PF/NC  [SC0402]
C106  3PF/NC  [SC0402]
C265  100NF/NC  [SC0603]
C372  10UF/NC  [SC0805]
C377  100NF  [SC0603]
D4  NC  [SC0402]
D5  NC  [SC0402]
D6  NC  [SC0402]
D7  NC  [SC0402]
J2  WIFI_2T2R  [SIP12-2_0MM-1827]
J7  USB-4S4  [USB4-200-1907]
J8  NC  [HSCOX-AMC-TM-A]
J9  NC  [HSCOX-AMC-TM-A]
J12  USB-4S4  [USB4-200-1907]
L1  1NH/NC  [SL0402]
L7  1NH/NC  [SL0402]
LB2  NC  [SL0603]
LB4  LB  [SL0805]
R106  22K  [SR0402]
R220  10K  [SR0402]
U2  NC  [CDTWIFI]
U7  NC  [CDTWIFI10]
U26  ETA6010  [SOT23-5]
sheet SHEET_14
C47  10UF  [SC0603]
C177  100NF/NC  [SC0402]
D3  IR  [SEN3-100C]
J3  NC  [SIP5-2MM]
LED1  LED2-3_E  [LED3C-100C]
Q1  NPN-BEC  [SOT23]
Q2  NPN-BEC  [SOT23]
R2  330  [SR0402]
R3  1K  [SR0402]
R22  10K  [SR0402]
R31  4.7K/NC  [SR0402]
R34  330  [SR0402]
R77  4.7K  [SR0402]
R140  10K  [SR0402]
R178  75  [SR0402]
sheet SHEET_15
C32  330N  [HSC0402]
C33  330N  [HSC0402]
C54  47PF  [SC0402]
C55  47PF  [SC0402]
C140  1NF  [SC0402]
C158  100NF  [SC0402]
C316  680PF  [SC0402]
C317  680PF  [SC0402]
C320  10UF  [SC0603]
C339  1NF  [SC0402]
C350  2.2UF  [SC0603]
C351  2.2UF  [SC0603]
C363  10UF  [SC0603]
R19  75K  [SR0603]
R20  75K  [SR0603]
R27  5.1K  [SR0603]
R28  5.1K  [SR0603]
R43  0  [SR0402]
R44  2.2K  [SR0402]
R48  5.6K  [SR0402]
R50  470K  [SR0402]
R66  470K  [SR0402]
R72  560  [HSR0402]
R74  560  [HSR0402]
R145  100K/NC  [SR0402]
R146  100K/NC  [SR0402]
R179  10  [SR0603]
R183  470K  [SR0402]
R193  20K  [SR0402]
R194  20K  [SR0402]
U5  SGM8903  [SGM8903]
sheet SHEET_16
C23  1NF  [SC1206]
C153  100NF  [SC0402]
C154  100NF  [SC0402]
C297  10NF/NC  [SC0402]
C307  10NF/NC  [SC0402]
J18  WBC1X41  [WBC0104-49T]
J25  MJ8-L  [MJ8-RLY]
R26  4.7K  [SR0402]
R30  4.7K  [SR0402]
R67  330  [SR0402]
R79  330  [SR0402]
R93  10  [SR0402]
R94  10  [SR0402]
R96  10  [SR0402]
R97  10  [SR0402]
R135  10K  [SR0402]
R136  10K  [SR0402]
R269  75  [SR0805]
R270  75  [SR0805]
R271  75  [SR0805]
R272  75  [SR0805]
T2  000-7090-37R  [STFM16-50-285]
U8  NC  [RN8-0402]
sheet SHEET_17
C17  180PF  [SC0402]
C79  180PF  [SC0402]
C80  100PF  [SC0402]
D9  D2-3_A  [SOT23]
J34  AV_JACK  [AV3-8-5-1]
L6  220NH  [SL0402]
R9  75  [SR0402]
sheet SHEET_18
C149  100NF  [SC0402]
C150  100NF  [SC0402]
D19  D_A  [HSOD323A]
D20  D_A  [HSOD323A]
J26  0  [WBC0119-20R-A]
R8  47K  [SR0402]
R186  2K  [SR0402]
R187  2K  [SR0402]
R268  27K  [SR0402]
U4  CS0806U  [SOT23A-6L]
U23  CS0806S  [DFN2510P10E]
U24  CS0806S  [DFN2510P10E]

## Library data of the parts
C28 C63 C93 C105 C123 C124 C133 C222 C223 C227-C240 C258 C323 C324 = C: %182%%238%%182%%168%%185%%164%%215%%247%%181%%231%%209%%185%(V): 10; %195%%232%%202%%246%: SMD陶瓷电容-10V-100NF-+/-10%-X5R-0402; %208%%161%%192%%224%%195%%251%%179%%198%: SMD陶瓷电容; CODE: 8070561; COMPONENT_HIGH_MAX: 0.55MM; DEVICE: C0402C104K8PAC_7867
C308 C310 = C: %182%%238%%182%%168%%185%%164%%215%%247%%181%%231%%209%%185%(V): 10; %195%%232%%202%%246%: SMD陶瓷电容-10V-1000NF-+/-10%-X5R-0402-BT,TS16949; %208%%161%%192%%224%%195%%251%%179%%198%: SMD陶瓷电容; CODE: 8070612; COMPONENT_HIGH_MAX: 0.55MM; DEVICE: CV05X5R105K10AH
C115 C314 = C: %182%%238%%182%%168%%185%%164%%215%%247%%181%%231%%209%%185%(V): 50; %195%%232%%202%%246%: SMD陶瓷电容-50V-1NF-+/-10%-X7R-0402-BT; %208%%161%%192%%224%%195%%251%%179%%198%: SMD陶瓷电容; CODE: 8070531; COMPONENT_HIGH_MAX: 0.56MM; DEVICE: 04025C102KAT2A
C15 C47 C319 C320 C363 = C: %182%%238%%182%%168%%185%%164%%215%%247%%181%%231%%209%%185%(V): 6.3; %195%%232%%202%%246%: SMD陶瓷电容-6.3V-10000NF-+/-20%-X5R-0603-BT,TS16949; %208%%161%%192%%224%%195%%251%%179%%198%: SMD陶瓷电容; CODE: 8070649; COMPONENT_HIGH_MAX: 0.9MM; DEVICE: C1608X5R0J106MT0A0E
C330 = C: %182%%238%%182%%168%%185%%164%%215%%247%%181%%231%%209%%185%(V): 16; %195%%232%%202%%246%: SMD陶瓷电容-16V-10NF-+/-10%-X7R-0402-BT,TS16949; %208%%161%%192%%224%%195%%251%%179%%198%: SMD陶瓷电容; CODE: 8070449; COMPONENT_HIGH_MAX: 0.56MM; DEVICE: GRM155R71C103KA01D
R16 R17 = R: %195%%232%%202%%246%: 片式厚膜电阻器-0.0625W-100OHM-±5%-0402; CODE: 7090807; COMPONENT_HIGH_MAX: 0.4MM; DEVICE: RC0402JR_07100R
R68 R69 R80 R90 R92 = R: %182%%238%%182%%168%%185%%166%%194%%202%(W): 0.06; %195%%232%%202%%246%: 片式厚膜电阻器-0.0625W-33OHM-+/-1%-0402; %208%%161%%192%%224%%195%%251%%179%%198%: 片式厚膜电阻器; %215%%232%%214%%181%%212%%202%%208%%237%%198%%171%%178%%238%: +/-1%; CODE: 7090836; COMPONENT_HIGH_MAX: 0.4MM; DEVICE: RC0402FR_0733RL
R71 = R: %182%%238%%182%%168%%185%%166%%194%%202%(W): 0.06; %195%%232%%202%%246%: 片式厚膜电阻器-0.0625W-240OHM-+/- 1%-0402-BT; %208%%161%%192%%224%%195%%251%%179%%198%: 片式厚膜电阻器; %215%%232%%214%%181%%212%%202%%208%%237%%198%%171%%178%%238%: +/- 1%; CODE: 7091782; COMPONENT_HIGH_MAX: 0.4MM; DEVICE: RC0402FR_07240RL
R76 R212 R220 = R: %182%%238%%182%%168%%185%%166%%194%%202%(W): 0.06; %195%%232%%202%%246%: 片式厚膜电阻器-0.0625W-10000OHM-+/-5%-0402-BT; %208%%161%%192%%224%%195%%251%%179%%198%: 片式厚膜电阻器; %215%%232%%214%%181%%212%%202%%208%%237%%198%%171%%178%%238%: +/-5%; CODE: 7090815; DEVICE: RC_02W103JT
R78 R84 R103 R107 = R: %182%%238%%182%%168%%185%%166%%194%%202%(W): 0.06; %195%%232%%202%%246%: 片式厚膜电阻器-0.0625W-1000OHM-+/-1%-0402-BT; %208%%161%%192%%224%%195%%251%%179%%198%: 片式厚膜电阻器; %215%%232%%214%%181%%212%%202%%208%%237%%198%%171%%178%%238%: +/-1%; CODE: 7091282; COMPONENT_HIGH_MAX: 0.4MM; DEVICE: RC0402FR_071KL
RN8-RN14 = RND8-4_5: %195%%232%%202%%246%: 电阻网络-0.0625W-33OHM-4个-8PIN-±5%-SMT-小型-独立式-2.0*1.0*0.45-0.5MM; %208%%161%%192%%224%%195%%251%%179%%198%: 电阻网络; %215%%232%%214%%181%%212%%202%%208%%237%%198%%171%%178%%238%: ±5%; CODE: 7080118; COMPONENT_HIGH_MAX: 0.55MM; DEVICE: YC124_JR_0733R
U6 = MT41J256M16RE-15E-D_4: %195%%232%%202%%246%: DDR3 DRAM-4GBIT-800MHZ-16BIT-1.5V-FBGA96(无铅); %208%%161%%192%%224%%195%%251%%179%%198%: DDR3 DRAM; CODE: 40020173; COMPONENT_HIGH_MAX: -99999999MM; DEVICE: H5TQ4G63MFR_PBC_A
C29 C60 = CP: %182%%238%%182%%168%%185%%164%%215%%247%%181%%231%%209%%185%(V): 16; %195%%232%%202%%246%: 非固体SMD铝电容-16V-100UF-+/-20%-6.3*5.4MM-极性-105DEGC-1000H-片式,温度敏感器件-工艺耐温250DEGC,5S; %208%%161%%192%%224%%195%%251%%179%%198%: 非固体SMD铝电容; CODE: 8010269; COMPONENT_HIGH_MAX: 5.7MM; DEVICE: UWT1C101MCL1GB
C36 = C: %182%%238%%182%%168%%185%%164%%215%%247%%181%%231%%209%%185%(V): 25; %195%%232%%202%%246%: SMD陶瓷电容-25V-1000NF-+/-10%-X7R-0603; %208%%161%%192%%224%%195%%251%%179%%198%: SMD陶瓷电容; CODE: 8070962; COMPONENT_HIGH_MAX: 0.9MM; DEVICE: CETMK107B7105KA_T
C100 C350 C351 = C: %182%%238%%182%%168%%185%%164%%215%%247%%181%%231%%209%%185%(V): 10; %195%%232%%202%%246%: SMD陶瓷电容-10V-2200NF-+/-10%-X5R-0603; %208%%161%%192%%224%%195%%251%%179%%198%: SMD陶瓷电容; CODE: 8070573; COMPONENT_HIGH_MAX: 0.9MM; DEVICE: GRM188R61A225KE34D
C142 C143 C153 C154 C158 = C: %182%%238%%182%%168%%185%%164%%215%%247%%181%%231%%209%%185%(V): 16; %195%%232%%202%%246%: SMD陶瓷电容-16V-100NF-±10%-X7R-0402; %208%%161%%192%%224%%195%%251%%179%%198%: SMD陶瓷电容; CODE: 8070614; COMPONENT_HIGH_MAX: 0.6MM; DEVICE: RMEMK105BJ104KV_FR
D1 = D_A: %195%%232%%202%%246%: 肖特基二极管-10V-3A-0.24V-SOD323-BT-5A; %208%%161%%192%%224%%195%%251%%179%%198%: 肖特基二极管; CODE: 15010252; COMPONENT_HIGH_MAX: 1.1MM; DEVICE: BAT60BE6327
LB6 = LB: %195%%232%%202%%246%: EMI磁珠-+/-25%-600OHM-0.65OHM-0.2A-402; %208%%161%%192%%224%%195%%251%%179%%198%: EMI磁珠; CODE: 10070013; COMPONENT_HIGH_MAX: 0.55MM; DEVICE: BLM15BD601SN1D
R8 R12 R29 R58 R176 R177 R188 R189 R202 R203 = R: %182%%238%%182%%168%%185%%166%%194%%202%(W): 0.06; %195%%232%%202%%246%: 片式厚膜电阻器-0.0625W-47000OHM-+/-5%-0402-ELOM; %208%%161%%192%%224%%195%%251%%179%%198%: 片式厚膜电阻器; %215%%232%%214%%181%%212%%202%%208%%237%%198%%171%%178%%238%: +/-5%; CODE: 7090819; DEVICE: RC0402JR_0747K
R43 R49 R57 = R: %182%%238%%182%%168%%185%%166%%194%%202%(W): 0.06; %195%%232%%202%%246%: 片式厚膜电阻器-0.0625W-0OHM-< 50MOHM-0402-1A-BT; %208%%161%%192%%224%%195%%251%%179%%198%: 片式厚膜电阻器; %215%%232%%214%%181%%212%%202%%208%%237%%198%%171%%178%%238%: < 50MOHM; CODE: 7090800; COMPONENT_HIGH_MAX: 0.4MM; DEVICE: RC0402JR_070R
R89 = R: %182%%238%%182%%168%%185%%166%%194%%202%(W): 0.06; %195%%232%%202%%246%: 片式厚膜电阻器-0.0625W-1000OHM-±5%-0402; %208%%161%%192%%224%%195%%251%%179%%198%: 片式厚膜电阻器; %215%%232%%214%%181%%212%%202%%208%%237%%198%%171%%178%%238%: ±5%; CODE: 7090809; COMPONENT_HIGH_MAX: 0.4MM; DEVICE: RC0402JR_071KL
R91 = R: %182%%238%%182%%168%%185%%166%%194%%202%(W): 0.1; %195%%232%%202%%246%: 片式厚膜电阻器-0.1W-2000OHM-+/-5%-0603; %208%%161%%192%%224%%195%%251%%179%%198%: 片式厚膜电阻器; %215%%232%%214%%181%%212%%202%%208%%237%%198%%171%%178%%238%: +/-5%; CODE: 7090643; COMPONENT_HIGH_MAX: 0.55MM; DEVICE: RC0603JR_072K
R26 R30 R215 = R: %182%%238%%182%%168%%185%%166%%194%%202%(W): 0.06; %195%%232%%202%%246%: 片式厚膜电阻器-0.0625W-4700OHM-+/-5%-0402; %208%%161%%192%%224%%195%%251%%179%%198%: 片式厚膜电阻器; %215%%232%%214%%181%%212%%202%%208%%237%%198%%171%%178%%238%: +/-5%; CODE: 7090793; COMPONENT_HIGH_MAX: 0.4MM; DEVICE: RK73B1ELTP472J
U19 = MLC_NAND_4: CODE: 40060145
U22 = M_0: CODE: 40060446; CaptureCellPackProp: MA
C50 C56 C88 C89 = C: %182%%238%%182%%168%%185%%164%%215%%247%%181%%231%%209%%185%(V): 50; %195%%232%%202%%246%: SMD陶瓷电容-50V-0.001NF-+/-0.1PF-NPO-0402-BT; %208%%161%%192%%224%%195%%251%%179%%198%: SMD陶瓷电容; CODE: 8070578; COMPONENT_HIGH_MAX: 0.55MM; DEVICE: GRM1555C1H1R0B
C61 C265 C377 = C: %182%%238%%182%%168%%185%%164%%215%%247%%181%%231%%209%%185%(V): 50; %195%%232%%202%%246%: SMD陶瓷电容-50V-100NF-±10%-X7R-0603; %208%%161%%192%%224%%195%%251%%179%%198%: SMD陶瓷电容; CODE: 8070627; COMPONENT_HIGH_MAX: 0.9MM; DEVICE: C1608X7R1H104KT000N
C103 C106 = C: %182%%238%%182%%168%%185%%164%%215%%247%%181%%231%%209%%185%(V): 50; %195%%232%%202%%246%: SMD陶瓷电容-50V-0.003NF-+/-0.25PF-NPO-0402; %208%%161%%192%%224%%195%%251%%179%%198%: SMD陶瓷电容; CODE: 8070636; COMPONENT_HIGH_MAX: 0.55MM; DEVICE: GRM1555C1H3R0CZ01D
C372 = C: %182%%238%%182%%168%%185%%164%%215%%247%%181%%231%%209%%185%(V): 25; %195%%232%%202%%246%: SMD陶瓷电容-25V-10000NF-+/-20%-X5R-0805; %208%%161%%192%%224%%195%%251%%179%%198%: SMD陶瓷电容; CODE: 8071629; COMPONENT_HIGH_MAX: 1.45MM; DEVICE: C2012X5R1E106KT000N1
D4-D7 = ULCE0505A015FR
J2 = WIFI_2T2R
J7 J12 = USB-4S4_0: %195%%232%%202%%246%: IO连接器-4+4PIN-插座/侧面插入型-屏蔽-A型USB插座; %208%%161%%192%%224%%195%%251%%179%%198%: IO连接器; CODE: 14240065; COMPONENT_HIGH_MAX: 15.08MM; DEVICE: UB31123_K1_4F
J8 J9 = COX-3_A: %195%%232%%202%%246%: 射频连接器-同轴连接器-50OHM-直式-MALE-SMT-终端专用-终端专用; %208%%161%%192%%224%%195%%251%%179%%198%: 射频连接器; CODE: 14240060; COMPONENT_HIGH_MAX: 1.45MM; DEVICE: 51_3612_50_H
L1 L7 = L: %195%%232%%202%%246%: 贴片电感器-0.001UH-5％-0.045OHM-1.36A-15DEGC-0402; %208%%161%%192%%224%%195%%251%%179%%198%: 贴片电感器; CODE: 10031232; COMPONENT_HIGH_MAX: 0.66MM; DEVICE: 0402CS_1N0XJLW
LB2 = LB: %195%%232%%202%%246%: EMI磁珠-30OHM-0.05OHM-0.4A-0603-; %208%%161%%192%%224%%195%%251%%179%%198%: EMI磁珠; CODE: 10070003; COMPONENT_HIGH_MAX: 0.95MM; DEVICE: MGLB1608_030T_LF
LB4 = LB: %195%%232%%202%%246%: EMI磁珠-+/-25%-220OHM-0.05OHM-2A-0805; %208%%161%%192%%224%%195%%251%%179%%198%: EMI磁珠; CODE: 10070012; COMPONENT_HIGH_MAX: 1.05MM; DEVICE: MGLB2012_220T_LF
R106 = R: %182%%238%%182%%168%%185%%166%%194%%202%(W): 0.06; %195%%232%%202%%246%: 片式厚膜电阻器-0.0625W-22000OHM-+/-1%-0402; %208%%161%%192%%224%%195%%251%%179%%198%: 片式厚膜电阻器; %215%%232%%214%%181%%212%%202%%208%%237%%198%%171%%178%%238%: +/-1%; CODE: 7090798; COMPONENT_HIGH_MAX: 0.4MM; DEVICE: RK73H1ELTP2202F
U2 = CDT-CELKF04
U7 = CDT-CELKF10_0
U26 = ETA6010_0
C149 C150 C177 = C: %182%%238%%182%%168%%185%%164%%215%%247%%181%%231%%209%%185%(V): 16; %195%%232%%202%%246%: SMD陶瓷电容-16V-100NF-+/-10%-X7R-0402-BT; %208%%161%%192%%224%%195%%251%%179%%198%: SMD陶瓷电容; CODE: 8070614; COMPONENT_HIGH_MAX: 0.6MM; DEVICE: RMEMK105BJ104KV_FR
D3 = IRM-3638A_0: %195%%232%%202%%246%: 红外遥控接收头-5V-0.001A-0.015KM-38KHZ-940NM-7*8*3.75; %208%%161%%192%%224%%195%%251%%179%%198%: 红外遥控接收头; COMPONENT_HIGH_MAX: 6.95MM; DEVICE: TSOP4838
J3 = SIP5: %195%%232%%202%%246%: 普通插座-5PIN-单排-直式-2MM-2MM-THT-3A; %208%%161%%192%%224%%195%%251%%179%%198%: 普通插座; CODE: *; DEVICE: P2500J_05
LED1 = LED2-3_E: %195%%232%%202%%246%: 发光二极管-0.25CD-红绿625NM/570NM-25MA-插装-共阴-终端专用-00500098; CODE: 15020190; COMPONENT_HIGH_MAX: 7.2MM; DEVICE: 209_3SYGSURC_S530_A3HW
Q1 Q2 = NPN-BEC: %195%%232%%202%%246%: 三极管-NPN-45V-100MA-225MW-200MV@100MA-SOT-23-180@2MA; %208%%161%%192%%224%%195%%251%%179%%198%: 三极管; CODE: 15050206; COMPONENT_HIGH_MAX: 1.26MM; DEVICE: BC847AE6327
R2 R34 R67 R79 = R: %182%%238%%182%%168%%185%%166%%194%%202%(W): 0.06; %195%%232%%202%%246%: 片式厚膜电阻器-0.0625W-330OHM-+/-1%-0402-BT; %208%%161%%192%%224%%195%%251%%179%%198%: 片式厚膜电阻器; %215%%232%%214%%181%%212%%202%%208%%237%%198%%171%%178%%238%: +/-1%; CODE: 7091333; COMPONENT_HIGH_MAX: 0.4MM; DEVICE: RC_02W3300FT
R3 = R: %182%%238%%182%%168%%185%%166%%194%%202%(W): 0.06; %195%%232%%202%%246%: 片式厚膜电阻器-0.0625W-1000OHM-+/-5%-0402-BT; %208%%161%%192%%224%%195%%251%%179%%198%: 片式厚膜电阻器; %215%%232%%214%%181%%212%%202%%208%%237%%198%%171%%178%%238%: +/-5%; CODE: 7090809; COMPONENT_HIGH_MAX: 0.4MM; DEVICE: RC0402JR_071KL
R22 R140 = R: %182%%238%%182%%168%%185%%166%%194%%202%(W): 0.06; %195%%232%%202%%246%: 片式厚膜电阻器-0.0625W-10000OHM-+/-5%-0402-BT; %208%%161%%192%%224%%195%%251%%179%%198%: 片式厚膜电阻器; %215%%232%%214%%181%%212%%202%%208%%237%%198%%171%%178%%238%: +/-5%; CODE: 7090815; COMPONENT_HIGH_MAX: 0.4MM; DEVICE: RC_02W103JT
R31 R77 = R: %182%%238%%182%%168%%185%%166%%194%%202%(W): 0.06; %195%%232%%202%%246%: 片式厚膜电阻器-0.0625W-4700OHM-+/-5%-0402-BT; %208%%161%%192%%224%%195%%251%%179%%198%: 片式厚膜电阻器; %215%%232%%214%%181%%212%%202%%208%%237%%198%%171%%178%%238%: +/-5%; CODE: 7090793; COMPONENT_HIGH_MAX: 0.4MM; DEVICE: RK73B1ELTP472J
R9 R178 = R: %182%%238%%182%%168%%185%%166%%194%%202%(W): 0.06; %195%%232%%202%%246%: 片式厚膜电阻器-0.0625W-75OHM-+/-1%-0402; %208%%161%%192%%224%%195%%251%%179%%198%: 片式厚膜电阻器; %215%%232%%214%%181%%212%%202%%208%%237%%198%%171%%178%%238%: +/-1%; CODE: 7091321; COMPONENT_HIGH_MAX: 0.4MM; DEVICE: RC_02W750FT
C32 C33 = C: %195%%232%%202%%246%: SMD陶瓷电容-6.3V-330NF-+/-10%-X5R-0402-终端专用; %208%%161%%192%%224%%195%%251%%179%%198%: SMD陶瓷电容; CODE: 8070953; COMPONENT_HIGH_MAX: 0.55MM; DEVICE: C1005X5R0J334K
C54 C55 = C: %182%%238%%182%%168%%185%%164%%215%%247%%181%%231%%209%%185%(V): 50; %195%%232%%202%%246%: SMD陶瓷电容-50V-0.047NF-+/-5%-NP0-0402; %208%%161%%192%%224%%195%%251%%179%%198%: SMD陶瓷电容; CODE: 8070549; COMPONENT_HIGH_MAX: 0.55MM; DEVICE: C0402C470J5GAC_7867
C140 C339 = C: %182%%238%%182%%168%%185%%164%%215%%247%%181%%231%%209%%185%(V): 50; %195%%232%%202%%246%: SMD陶瓷电容-50V-1NF-+/-10%-X7R-0402-BT; %208%%161%%192%%224%%195%%251%%179%%198%: SMD陶瓷电容; CODE: 8070531; COMPONENT_HIGH_MAX: 0.55MM; DEVICE: 04025C102KAT2A
C316 C317 = C: %182%%238%%182%%168%%185%%164%%215%%247%%181%%231%%209%%185%(V): 50; %195%%232%%202%%246%: SMD陶瓷电容-50V-0.68NF-+/-5%-NP0-0402-供电专用-供电专用; %208%%161%%192%%224%%195%%251%%179%%198%: SMD陶瓷电容; CODE: 8070853; COMPONENT_HIGH_MAX: 0.55MM; DEVICE: C0402C681J5GAC7867
R19 R20 = R: %182%%238%%182%%168%%185%%166%%194%%202%(W): 0.1; %195%%232%%202%%246%: 片式厚膜电阻器-0.1W-75000OHM-+/-1% -0603; %208%%161%%192%%224%%195%%251%%179%%198%: 片式厚膜电阻器; %215%%232%%214%%181%%212%%202%%208%%237%%198%%171%%178%%238%: +/-1%; CODE: 7091238; COMPONENT_HIGH_MAX: 0.55MM; DEVICE: RK73H1JTTD7502F
R27 R28 = R: %182%%238%%182%%168%%185%%166%%194%%202%(W): 0.1; %195%%232%%202%%246%: 片式厚膜电阻器-0.1W-5100OHM-+/-1%-0603; %208%%161%%192%%224%%195%%251%%179%%198%: 片式厚膜电阻器; %215%%232%%214%%181%%212%%202%%208%%237%%198%%171%%178%%238%: +/-1%; CODE: 7091295; COMPONENT_HIGH_MAX: 0.55MM; DEVICE: RC0603FR_075K1L
R44 = R: %182%%238%%182%%168%%185%%166%%194%%202%(W): 0.06; %195%%232%%202%%246%: 片式厚膜电阻器-0.0625W-2200OHM-+/-1%-0402--供电专用-07090810-供电专用; %208%%161%%192%%224%%195%%251%%179%%198%: 片式厚膜电阻器; %215%%232%%214%%181%%212%%202%%208%%237%%198%%171%%178%%238%: +/-1%; CODE: 7091537; COMPONENT_HIGH_MAX: 0.4MM; DEVICE: RC0402FR_072K2L2
R48 = R: %182%%238%%182%%168%%185%%166%%194%%202%(W): 0.06; %195%%232%%202%%246%: 片式厚膜电阻器-0.0625W-5600OHM-+/-1%-0402-BT; %208%%161%%192%%224%%195%%251%%179%%198%: 片式厚膜电阻器; %215%%232%%214%%181%%212%%202%%208%%237%%198%%171%%178%%238%: +/-1%; CODE: 7091275; COMPONENT_HIGH_MAX: 0.4MM; DEVICE: RK73H1ETTP5601F
R50 R183 = R: %182%%238%%182%%168%%185%%166%%194%%202%(W): 0.06; %195%%232%%202%%246%: 片式厚膜电阻器-0.0625W-470000OHM-±1%-0402; %208%%161%%192%%224%%195%%251%%179%%198%: 片式厚膜电阻器; %215%%232%%214%%181%%212%%202%%208%%237%%198%%171%%178%%238%: ±1%; CODE: 7090855; COMPONENT_HIGH_MAX: 0.4MM; DEVICE: RK73H1ETTP4703F
R66 = R: %182%%238%%182%%168%%185%%166%%194%%202%(W): 0.06; %195%%232%%202%%246%: 片式厚膜电阻器-0.0625W-470000OHM-+/-1%-0402; %208%%161%%192%%224%%195%%251%%179%%198%: 片式厚膜电阻器; %215%%232%%214%%181%%212%%202%%208%%237%%198%%171%%178%%238%: +/-1%; CODE: 7090855; COMPONENT_HIGH_MAX: 0.4MM; DEVICE: RK73H1ETTP4703F
R72 R74 = R: %195%%232%%202%%246%: 片式厚膜电阻器-0.0625W-560OHM-+/-5%-0402-终端专用-终端专用; %208%%161%%192%%224%%195%%251%%179%%198%: 片式厚膜电阻器; CODE: 7091285; COMPONENT_HIGH_MAX: 0.4MM; DEVICE: RC0402JR_07560RL
R145 R146 = R: %182%%238%%182%%168%%185%%166%%194%%202%(W): 0.06; %195%%232%%202%%246%: 片式厚膜电阻器-0.0625W-100000OHM-+/-5%-0402-BT; %208%%161%%192%%224%%195%%251%%179%%198%: 片式厚膜电阻器; %215%%232%%214%%181%%212%%202%%208%%237%%198%%171%%178%%238%: +/-5%; CODE: 7090831; COMPONENT_HIGH_MAX: 0.4MM; DEVICE: RK73B1ELTP104J
R179 = R: %182%%238%%182%%168%%185%%166%%194%%202%(W): 0.1; %195%%232%%202%%246%: 片式厚膜电阻器-0.1W-10OHM-+/-5%-0603-TS16949; %208%%161%%192%%224%%195%%251%%179%%198%: 片式厚膜电阻器; %215%%232%%214%%181%%212%%202%%208%%237%%198%%171%%178%%238%: +/-5%; CODE: 7090264; COMPONENT_HIGH_MAX: 0.55MM; DEVICE: RC0603JR_0710R
R193 R194 = R: %182%%238%%182%%168%%185%%166%%194%%202%(W): 0.06; %195%%232%%202%%246%: 片式厚膜电阻器-0.0625W-20000OHM-+/-1%-0402-TS16949; %208%%161%%192%%224%%195%%251%%179%%198%: 片式厚膜电阻器; %215%%232%%214%%181%%212%%202%%208%%237%%198%%171%%178%%238%: +/-1%; CODE: 7091374; COMPONENT_HIGH_MAX: 0.4MM; DEVICE: RC_02W2002FT
U5 = SGM8903
C23 = C: %182%%238%%182%%168%%185%%164%%215%%247%%181%%231%%209%%185%(V): 2000; %195%%232%%202%%246%: SMD陶瓷电容-2000V-1NF-+/-20%-X7R-1206; %208%%161%%192%%224%%195%%251%%179%%198%: SMD陶瓷电容; CODE: 8070439; COMPONENT_HIGH_MAX: 1.52MM; DEVICE: 1206GC102MAT1A
C297 C307 = C: %182%%238%%182%%168%%185%%164%%215%%247%%181%%231%%209%%185%(V): 16; %195%%232%%202%%246%: SMD陶瓷电容-16V-10NF-+/-10%-X7R-0402-BT,TS16949; %208%%161%%192%%224%%195%%251%%179%%198%: SMD陶瓷电容; CODE: 8070449; COMPONENT_HIGH_MAX: 0.55MM; DEVICE: GRM155R71C103KA01D
J18 = WBC1X41: %195%%232%%202%%246%: 普通插座-4PIN-单排-直式-1.25MM-2MM-THT-1A; %208%%161%%192%%224%%195%%251%%179%%198%: 普通插座; CODE: 14100167; COMPONENT_HIGH_MAX: 4.2MM; DEVICE: SDW12501_4A_HW
J25 = MJ8-L_1: %195%%232%%202%%246%: 网口连接器-单排-单端口-8PIN-8BIT-非屏蔽-模型插座/侧面插入型-引脚长2.54MM-带固定脚/带灯; %208%%161%%192%%224%%195%%251%%179%%198%: 网口连接器; COMPONENT_HIGH_MAX: 13.2MM; DEVICE: 406533_1
R93 R94 R96 R97 = R: %182%%238%%182%%168%%185%%166%%194%%202%(W): 0.06; %195%%232%%202%%246%: 片式厚膜电阻器-0.0625W-10OHM-+/-5%-0402; %208%%161%%192%%224%%195%%251%%179%%198%: 片式厚膜电阻器; %215%%232%%214%%181%%212%%202%%208%%237%%198%%171%%178%%238%: +/-5%; CODE: 7090730; COMPONENT_HIGH_MAX: 0.4MM; DEVICE: RC0402JR_0710R
R135 R136 = R: %182%%238%%182%%168%%185%%166%%194%%202%(W): 0.06; %195%%232%%202%%246%: 片式厚膜电阻器-0.0625W-10000OHM-±5%-0402; %208%%161%%192%%224%%195%%251%%179%%198%: 片式厚膜电阻器; %215%%232%%214%%181%%212%%202%%208%%237%%198%%171%%178%%238%: ±5%; CODE: 7090815; COMPONENT_HIGH_MAX: 0.4MM; DEVICE: RC_02W103JT
R269-R272 = R: %182%%238%%182%%168%%185%%166%%194%%202%(W): 0.13; %195%%232%%202%%246%: 片式厚膜电阻器-0.125W-75OHM-±1%-0805; %208%%161%%192%%224%%195%%251%%179%%198%: 片式厚膜电阻器; %215%%232%%214%%181%%212%%202%%208%%237%%198%%171%%178%%238%: ±1%; CODE: 7090362; DEVICE: RC0805FR_0775R
T2 = 000-7090-37R: %195%%232%%202%%246%: LAN变压器-1CT:1CT-0.35MH-0UH-1路-2变压器-100BASE-T接口模块-SMT; %208%%161%%192%%224%%195%%251%%179%%198%: LAN变压器; CODE: 9050085; COMPONENT_HIGH_MAX: 6.2MM; DEVICE: H1102T
U8 = CS2203-25
C17 C79 = C: %182%%238%%182%%168%%185%%164%%215%%247%%181%%231%%209%%185%(V): 50; %195%%232%%202%%246%: SMD陶瓷电容-50V-0.18NF-+/-5%-NPO-0402; %208%%161%%192%%224%%195%%251%%179%%198%: SMD陶瓷电容; CODE: 8070637; COMPONENT_HIGH_MAX: 0.55MM; DEVICE: CC0402JRNPO9BB181
C80 = C: %182%%238%%182%%168%%185%%164%%215%%247%%181%%231%%209%%185%(V): 50; %195%%232%%202%%246%: SMD陶瓷电容-50V-0.1NF-±5%-NPO-0402; %208%%161%%192%%224%%195%%251%%179%%198%: SMD陶瓷电容; CODE: 8070450; COMPONENT_HIGH_MAX: 0.55MM; DEVICE: 04025A101JAT2A
D9 = D2-3_A: %195%%232%%202%%246%: 开关二极管-70V-200MA-1.25V-6NS-串联-SOT-23-2 FIT; %208%%161%%192%%224%%195%%251%%179%%198%: 开关二极管; CODE: 15010042; COMPONENT_HIGH_MAX: 1.26MM; DEVICE: BAV99B5003
J34 = AV_JACK
L6 = L: %195%%232%%202%%246%: 贴片电感器-0.22UH-+/-5%-3.77OHM-0.3A-0402; %208%%161%%192%%224%%195%%251%%179%%198%: 贴片电感器; CODE: 10031264; COMPONENT_HIGH_MAX: 0.55MM; DEVICE: LGHK1005R22J_T
D19 D20 = D_A: %195%%232%%202%%246%: 肖特基二极管-10V-3A-0.24V-SOD323-BT; %208%%161%%192%%224%%195%%251%%179%%198%: 肖特基二极管; CODE: 15010252; COMPONENT_HIGH_MAX: 1.1MM; DEVICE: BAT60BE6327
J26 = WBC1X19S4M2_0: %195%%232%%202%%246%: IO连接器-HDMI 母座-19PIN-弯式-SMT带DIP脚-终端专用; %208%%161%%192%%224%%195%%251%%179%%198%: IO连接器; CODE: 14240146; COMPONENT_HIGH_MAX: 6.38MM; DEVICE: 1827059_3
R186 R187 = R: %182%%238%%182%%168%%185%%166%%194%%202%(W): 0.06; %195%%232%%202%%246%: 片式厚膜电阻器-0.0625W-2000OHM-+/-1%-0402-BT; %208%%161%%192%%224%%195%%251%%179%%198%: 片式厚膜电阻器; %215%%232%%214%%181%%212%%202%%208%%237%%198%%171%%178%%238%: +/-1%; CODE: 7091354; COMPONENT_HIGH_MAX: 0.4MM; DEVICE: RC_02W2001FT
R268 = R: %182%%238%%182%%168%%185%%166%%194%%202%(W): 0.06; %195%%232%%202%%246%: 片式厚膜电阻器-0.0625W-27000OHM-+/-5%-0402; %208%%161%%192%%224%%195%%251%%179%%198%: 片式厚膜电阻器; %215%%232%%214%%181%%212%%202%%208%%237%%198%%171%%178%%238%: +/-5%; CODE: 7090852; COMPONENT_HIGH_MAX: 0.4MM; DEVICE: RK73B1ETTP273J
U4 = CS0806U
U23 = CS0806S: #: 3
U24 = CS0806S

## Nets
1V5_DDR3: C28.1(A) C133.1(A) C222.1(A) C223.1(A) C227.1(A) C228.1(A) C229.1(A) C230.1(A) C231.1(A) C232.1(A) C233.1(A) C234.1(A) C235.1(A) C236.1(A) C237.1(A) C238.1(A) C239.1(A) C240.1(A) C258.1(A) C319.1(A) R76.1(A) R78.1(A) R103.1(A) U6.A1(VDDQ1) U6.A8(VDDQ2) U6.B2(VDD1) U6.C1(VDDQ3) U6.C9(VDDQ4) U6.D2(VDDQ5) U6.D9(VDD2) U6.E9(VDDQ6) U6.F1(VDDQ7) U6.G7(VDD3) U6.H2(VDDQ8) U6.H9(VDDQ9) U6.K2(VDD4) U6.K8(VDD5) U6.N1(VDD6) U6.N9(VDD7) U6.R1(VDD8) U6.R9(VDD9) ; also on sheet 9 11 15
3V3: J18.4 R2.1(A) R31.1(A) R34.1(A) R135.1(A) R136.2(B) R140.2(B) R178.2(B) ; also on sheet 10 13 14 15
3V3_IR: C47.1(A) C177.1(A) D3.3(VCC) J3.2(A2) R178.1(A)
3V3_MOS: D1.2(A) D9.2(K) D19.2(A) J25.10 J25.12 LB4.2 LB6.1 R26.1(A) R30.1(A) ; also on sheet 10 11 12 13 14
3V3_MOS_FLASH: C29.1 C36.1(A) C63.1(A) C93.1(A) C100.1(A) C105.1(A) C142.1(A) C143.1(A) C323.1(A) C324.1(A) D1.1(K) LB6.2 R12.1(A) R29.1(A) R49.1(A) R57.2(B) R58.1(A) R91.1(A) R176.1(A) R177.1(A) R188.1(A) R189.1(A) R202.1(A) R203.1(A) R212.1(A) R215.1(A) U19.1(NC1/VDD3) U19.12(VDD1) U19.24(NC15/VDD4) U19.34(NC21/VDDQ1) U19.37(VDD2) U22.AA3(VDD_4) U22.AA5(VDD_5) U22.K6(VDD_1) U22.M6(VDDF_1) U22.N5(VDDF_2) U22.T10(VDDF_3) U22.U9(VDDF_4) U22.W4(VDD_2) U22.Y4(VDD_3)
3V3_WIFI: C15.1(A) C61.1(A) J2.5(DVDD33) LB4.1 U2.5(VDD3.3) U7.8(VDD3.3)
5V0_MOS: C377.1(A) D20.2(A) LB2.2 R179.1(A) R220.2(B) U26.1(IN) ; also on sheet 14
5V0_MOS_HDMI: C150.1(A) D20.1(K) J26.18 R186.2(B) R187.2(B) U4.5(VDD)
GND: C15.2(B) C17.2(B) C23.2(B) C28.2(B) C29.2 C33.1(A) C36.2(B) C47.2(B) C50.2(B) C56.2(B) C60.2 C61.2(B) C63.2(B) C79.2(B) C88.2(B) C89.2(B) C93.2(B) C100.2(B) C103.2(B) C105.2(B) C106.2(B) C115.2(B) C123.2(B) C124.2(B) C133.2(B) C140.2(B) C142.2(B) C143.2(B) C149.2(B) C150.2(B) C153.2(B) C154.2(B) C158.2(B) C177.2(B) C227.2(B) C228.2(B) C229.2(B) C230.2(B) C231.2(B) C232.2(B) C233.2(B) C234.2(B) C235.2(B) C236.2(B) C237.2(B) C238.2(B) C239.2(B) C240.2(B) C258.2(B) C265.2(B) C297.2(B) C307.2(B) C308.2(B) C310.2(B) C314.2(B) C316.2(B) C317.2(B) C319.2(B) C320.2(B) C323.2(B) C324.2(B) C330.2(B) C339.2(B) C363.2(B) C372.2(B) C377.2(B) D3.2(GND) D4.2(B) D5.2(B) D6.2(B) D7.2(B) D9.1(A) J2.2(GND1) J2.7(GND5) J2.9(GND3) J2.10(GND2) J2.12(GND4) J3.4(A4) J7.4 J7.5(S1) J7.6(S2) J7.7(S3) J7.8(S4) J8.2 J8.3 J9.2 J9.3 J12.4 J12.5(S1) J12.6(S2) J12.7(S3) J12.8(S4) J18.1 J26.2 J26.5 J26.8 J26.11 J26.17 J26.20(S1) J26.21(S2) J26.22(S3) J26.23(S4) J34.6(GND3) J34.7(GND4) J34.8(GND5) LED1.2(C) Q1.2(E) Q2.2(E) R8.1(A) R9.2(B) R44.2(B) R50.2(B) R71.1(A) R77.2(B) R84.2(B) R89.2(B) R91.2(B) R106.1(A) R107.2(B) R145.2(B) R146.2(B) R183.2(B) RN8.3 RN8.6 RN9.3 RN9.6 RN10.2 RN10.7 RN11.3 RN11.6 RN12.2 RN12.7 RN13.3 RN13.6 RN14.2 RN14.7 U2.1(GND) U2.6(RFGND) U4.2(GND) U5.1(+INR) U5.4(SGND) U5.10(PGND) U5.14(+INL) U6.A9(VSS1) U6.B1(VSSQ1) U6.B3(VSS2) U6.B9(VSSQ2) U6.D1(VSSQ3) U6.D8(VSSQ4) U6.E1(VSS3) U6.E2(VSSQ5) U6.E8(VSSQ6) U6.F9(VSSQ7) U6.G1(VSSQ8) U6.G8(VSS4) U6.G9(VSSQ9) U6.J2(VSS5) U6.J8(VSS6) U6.M1(VSS7) U6.M9(VSS8) U6.P1(VSS9) U6.P9(VSS10) U6.T1(VSS11) U6.T9(VSS12) U7.1(RFGND1) U7.5(GND) U19.2(NC2/VSS3) U19.13(VSS1) U19.23(NC14/VSS4) U19.25(NC16/VSS5) U19.36(VSS2) U19.48(NC29/VSS6) U22.AA4(VSS_8) U22.AA6(VSS_9) U22.K4(VSS_1) U22.M7(VSS_2) U22.P5(VSS_3) U22.R10(VSS_4) U22.U8(VSS_5) U22.Y2(VSS_6) U22.Y5(VSS_7) U23.3(GND1) U23.8(GND2) U24.3(GND1) U24.8(GND2) U26.2(GND) ; also on sheet 9 10 11 12 13 14 15 16
VDD_AUDIO: C158.1(A) C320.1(A) R48.1(A) R66.2(B) R179.2(B) U5.9(PVDD)
ADAC_VOUTL: C350.2(B) R50.1(A) ; also on sheet 12
ADAC_VOUTR: C351.1(A) R183.1(A) ; also on sheet 12
AUDIO_L: C339.1(A) J34.2(AL) R72.2(B)
AUDIO_R: C140.1(A) J34.1(AR) R74.1(A)
CVBS: C79.1(A) C80.1(A) L6.1(A) R9.1(A) ; also on sheet 12
CVBS_OUT: C17.1(A) C80.2(B) D9.3(COM) J34.3(CVBS) L6.2(B)
DDR_ADDR0: RN11.8 ; also on sheet 9 11
DDR_ADDR0_B: RN11.1 U6.N3(A0)
DDR_ADDR1: RN13.5 ; also on sheet 9 11
DDR_ADDR1_B: RN13.4 U6.P7(A1)
DDR_ADDR2: R69.1(A) ; also on sheet 9 11
DDR_ADDR2_B: R69.2(B) U6.P3(A2)
DDR_ADDR3: RN11.7 ; also on sheet 9 11
DDR_ADDR3_B: RN11.2 U6.N2(A3)
DDR_ADDR4: R90.1(A) ; also on sheet 9 11
DDR_ADDR4_B: R90.2(B) U6.P8(A4)
DDR_ADDR5: RN11.5 ; also on sheet 9 11
DDR_ADDR5_B: RN11.4 U6.P2(A5)
DDR_ADDR6: RN13.7 ; also on sheet 9 11
DDR_ADDR6_B: RN13.2 U6.R8(A6)
DDR_ADDR7: R68.1(A) ; also on sheet 9 11
DDR_ADDR7_B: R68.2(B) U6.R2(A7)
DDR_ADDR8: RN13.8 ; also on sheet 9 11
DDR_ADDR8_B: RN13.1 U6.T8(A8)
DDR_ADDR9: RN9.7 ; also on sheet 9 11
DDR_ADDR9_B: RN9.2 U6.R3(A9)
DDR_ADDR10: RN8.5 ; also on sheet 9 11
DDR_ADDR10_B: RN8.4 U6.L7(A10/AP)
DDR_ADDR11: RN10.6 ; also on sheet 9 11
DDR_ADDR11_B: RN10.3 U6.R7(A11)
DDR_ADDR12: RN8.7 ; also on sheet 9 11
DDR_ADDR12_B: RN8.2 U6.N7(A12/BC~)
DDR_ADDR13: RN9.5 ; also on sheet 9 11
DDR_ADDR13_B: RN9.4 U6.T3(A13)
DDR_ADDR14: RN10.5 ; also on sheet 9 11
DDR_ADDR14_B: RN10.4 U6.T7(A14)
DDR_ADDR15: RN10.8 ; also on sheet 9 11
DDR_ADDR15_B: RN10.1 U6.M7(NC5)
DDR_BA0: RN14.5 ; also on sheet 9 11
DDR_BA0_B: RN14.4 U6.M2(BA0)
DDR_BA1: RN8.8 ; also on sheet 9 11
DDR_BA1_B: RN8.1 U6.N8(BA1)
DDR_BA2: RN12.8 ; also on sheet 9 11
DDR_BA2_B: RN12.1 U6.M3(BA2)
DDR_CASN: RN12.5 ; also on sheet 9 11
DDR_CASN_B: RN12.4 U6.K3(~{CAS})
DDR_CKE: R92.1(A) ; also on sheet 9 11
DDR_CKE_B: R92.2(B) U6.K9(CKE)
DDR_CLK1N: R16.1(A) U6.K7(~{CK}) ; also on sheet 11
DDR_CLK1P: R17.2(B) U6.J7(CK) ; also on sheet 11
DDR_CSN: R80.1(A) ; also on sheet 9 11
DDR_CSN_B: R80.2(B) U6.L2(~{CS})
DDR_DM2: U6.E7(LDM) ; also on sheet 11
DDR_DM3: U6.D3(UDM) ; also on sheet 11
DDR_DQ16: U6.E3(DQ0) ; also on sheet 11
DDR_DQ17: U6.F7(DQ1) ; also on sheet 11
DDR_DQ18: U6.F2(DQ2) ; also on sheet 11
DDR_DQ19: U6.F8(DQ3) ; also on sheet 11
DDR_DQ20: U6.H3(DQ4) ; also on sheet 11
DDR_DQ21: U6.H8(DQ5) ; also on sheet 11
DDR_DQ22: U6.G2(DQ6) ; also on sheet 11
DDR_DQ23: U6.H7(DQ7) ; also on sheet 11
DDR_DQ24: U6.D7(DQ8) ; also on sheet 11
DDR_DQ25: U6.C3(DQ9) ; also on sheet 11
DDR_DQ26: U6.C8(DQ10) ; also on sheet 11
DDR_DQ27: U6.C2(DQ11) ; also on sheet 11
DDR_DQ28: U6.A7(DQ12) ; also on sheet 11
DDR_DQ29: U6.A2(DQ13) ; also on sheet 11
DDR_DQ30: U6.B8(DQ14) ; also on sheet 11
DDR_DQ31: U6.A3(DQ15) ; also on sheet 11
DDR_DQS2N: U6.G3(~{LDQS}) ; also on sheet 11
DDR_DQS2P: U6.F3(LDQS) ; also on sheet 11
DDR_DQS3N: U6.B7(~{UDQS}) ; also on sheet 11
DDR_DQS3P: U6.C7(UDQS) ; also on sheet 11
DDR_ODT: RN14.6 ; also on sheet 9 11
DDR_ODT_B: RN14.3 U6.K1(ODT)
DDR_RASN: RN14.8 ; also on sheet 9 11
DDR_RASN_B: RN14.1 U6.J3(~{RAS})
DDR_RESETN: RN9.8 ; also on sheet 9 11
DDR_RESETN_B: C314.1(A) R76.2(B) RN9.1 U6.T2(~{RESET})
DDR_VREF_CA_B: C222.2(B) C310.1(A) R103.2(B) R107.1(A) U6.M8(VREFCA)
DDR_VREF_DQ_B: C223.2(B) C308.1(A) R78.2(B) R84.1(A) U6.H1(VREFDQ)
DDR_WEN: RN12.6 ; also on sheet 9 11
DDR_WEN_B: RN12.3 U6.L3(~{WE})
HDMI_TX0N: J26.9 U24.2(IO2_IN) U24.9(IO2_OUT) ; also on sheet 12
HDMI_TX0P: J26.7 U24.1(IO1_IN) U24.10(IO1_OUT) ; also on sheet 12
HDMI_TX1N: J26.6 U23.5(IO4_IN) U23.6(IO4_OUT) ; also on sheet 12
HDMI_TX1P: J26.4 U23.4(IO3_IN) U23.7(IO3_OUT) ; also on sheet 12
HDMI_TX2N: J26.3 U23.2(IO2_IN) U23.9(IO2_OUT) ; also on sheet 12
HDMI_TX2P: J26.1 U23.1(IO1_IN) U23.10(IO1_OUT) ; also on sheet 12
HDMI_TX_CEC: J26.13 R268.2(B) U4.3(I/O2) ; also on sheet 12
HDMI_TX_HOTPLUG: C149.1(A) J26.19 R8.2(B) U4.4(I/O3) ; also on sheet 12
HDMI_TX_SCL: J26.15 R186.1(A) U4.1(I/O1) ; also on sheet 12
HDMI_TX_SDA: J26.16 R187.1(A) U4.6(I/O4) ; also on sheet 12
HDMI_TXCN: J26.12 U24.5(IO4_IN) U24.6(IO4_OUT) ; also on sheet 12
HDMI_TXCP: J26.10 U24.4(IO3_IN) U24.7(IO3_OUT) ; also on sheet 12
IR_IN: D3.1(OUT) J3.3(A3) R140.1(A) ; also on sheet 12
LED0_BASE: R26.2(B) R67.2(B) ; also on sheet 13
LED0_LINK_ACT: R30.2(B) R79.2(B) ; also on sheet 13
LED_CTRL: R3.1(A) R31.2(B) R77.1(A) ; also on sheet 12
LED_GREEN: J3.1(A1) LED1.3(A2) Q2.3(C) R34.2(B)
LED_RED: J3.5(A5) LED1.1(A1) Q1.3(C) R2.2(B) R22.1(A)
NF_ALE_EMMC_PWREN: U19.17(ALE) ; also on sheet 13
NF_CLE: U19.16(CLE) ; also on sheet 13
NF_CSN0_EMMC_CMD: R212.2(B) U19.9(~{CE}) U22.W5(CMD) ; also on sheet 13
NF_DQ0_EMMC_D0: R189.2(B) U19.29(I/O0) U22.H3(DAT0) ; also on sheet 13
NF_DQ1_EMMC_D1: R12.2(B) U19.30(I/O1) U22.H4(DAT1) ; also on sheet 13
NF_DQ2_EMMC_D2: R29.2(B) U19.31(I/O2) U22.H5(DAT2) ; also on sheet 13
NF_DQ3_EMMC_D3: R58.2(B) U19.32(I/O3) U22.J2(DAT3) ; also on sheet 13
NF_DQ4_EMMC_D4: R176.2(B) U19.41(I/O4) U22.J3(DAT4) ; also on sheet 13
NF_DQ5_EMMC_D5: R177.2(B) U19.42(I/O5) U22.J4(DAT5) ; also on sheet 13
NF_DQ6_EMMC_D6: R188.2(B) U19.43(I/O6) U22.J5(DAT6) ; also on sheet 13
NF_DQ7_EMMC_D7_BOOT_SEL0: R202.2(B) U19.44(I/O7) U22.J6(DAT7) ; also on sheet 13
NF_RDY0_EMMC_RST: C115.1(A) R203.2(B) U19.7(R/B~) U22.U5(RSTN) ; also on sheet 13
NF_REN_EMMC_CLK: U19.8(~{RE}) U22.W6(CLK) ; also on sheet 13
NF_WEN_EMMC_DET: U19.18(~{WE}) ; also on sheet 13
NF_WP: R89.1(A) R215.2(B) U19.19(~{WP})
RF0: C89.1(A) L1.2(B) U7.3(RF0)
RF1: C56.1(A) L7.2(B) U2.7(RF) U7.2(RF1)
RFF0: C88.1(A) J9.1 L1.1(A)
RFF1: C50.1(A) J8.1 L7.1(A)
RX+_PHY0: R97.1(A) U8.2(IO1_N1) U8.7(IO1_N2) ; also on sheet 13
RX-_PHY0: R96.1(A) U8.1(IO1_P1) U8.8(IO1_P2) ; also on sheet 13
TX+_PHY0: R93.1(A) U8.4(IO2_N1) U8.5(IO2_N2) ; also on sheet 13
TX-_PHY0: R94.1(A) U8.3(IO2_P1) U8.6(IO2_P2) ; also on sheet 13
UART0_RXD: J18.2 R136.1(A) ; also on sheet 12
UART0_TXD: J18.3 R135.2(B) ; also on sheet 12
USB0_DM: C103.1(A) D5.1(A) J12.2 ; also on sheet 13
USB0_DP: C106.1(A) D4.1(A) J12.3 ; also on sheet 13
USB1_DM: J2.4(D-) U2.4(DM) U7.7(DM) ; also on sheet 13
USB1_DP: J2.3(D+) U2.2(DP) U7.6(DP) ; also on sheet 13
USB2_DM: D7.1(A) J7.2 ; also on sheet 12
USB2_DP: D6.1(A) J7.3 ; also on sheet 12
USB03_VBUS: C60.1 C265.1(A) C372.1(A) J7.1 J12.1 LB2.1 U26.5(OUT)
N302811: D19.1(K) R268.1(A)
N318278: R93.2(B) T2.1(TD+)
N318284: R94.2(B) T2.3(TD-)
N318290: R97.2(B) T2.6(RD+)
N318296: R96.2(B) T2.8(RD-)
N318334: C153.1(A) C307.1(A) T2.2(CTD)
N318352: J25.4 J25.5 R272.2(B)
N318370: J25.2 T2.14(TX-)
N318384: J25.1 T2.16(TX+)
N318398: C23.1(A) R269.1(A) R270.1(A) R271.1(A) R272.1(A)
N318436: J25.3 T2.11(RX+)
N318450: J25.6 T2.9(RX-)
N318456: R269.2(B) T2.10(CRX)
N318466: R271.2(B) T2.15(CTX)
N318476: J25.7 J25.8 R270.2(B)
N318494: J25.11 R79.1(A)
N318500: J25.9 R67.1(A)
N318506: C154.1(A) C297.1(A) T2.7(CRD)
N333425: C32.2(B) U5.8(CP)
N333437: C33.2(B) U5.6(PVSS)
N333441: C32.1(A) U5.7(CN)
N333453: R43.1(A) U5.11(UVP)
N333457: R43.2(B) R44.1(A) R48.2(B)
N333491: C316.1(A) R20.2(B) R28.2(B) R194.1(A)
N333511: C350.1(A) R194.2(B)
N333529: C54.1(A) R20.1(A) R72.1(A) R145.1(A) U5.12(OUTL)
N333561: C54.2(B) R28.1(A) U5.13(-INL)
N333577: C55.2(B) R19.2(B) R74.2(B) R146.1(A) U5.3(OUTR)
N333623: C317.1(A) R19.1(A) R27.1(A) R193.2(B)
N333657: C55.1(A) R27.2(B) U5.2(-INR)
N333673: C351.2(B) R193.1(A)
N333677: C363.1(A) R66.1(A) U5.5(EN)
N341400: Q1.1(B) R3.2(B)
N341404: Q2.1(B) R22.2(B)
N348576: R106.2(B) U26.4(ILIM)
N348702: R220.1(A) U26.3(EN)
N357628: R57.1(A) U19.39(NC24)
N359588: C123.1(A) C124.1(A) U22.K2(VDDI)
N359622: R49.2(B) U19.38(NC23/VDDQ2)
N371714: R71.2(B) U6.L8(ZQ)
N374550: C330.1(A) R16.2(B) R17.1(A)

Not connected (* = marked no-connect by the designer): J2 1(NC1) 6(NC2) 8(RF0) 11(RF1); J25 13(M1) 14(M2); J26 14 24(M1) 25(M2); J34 4(GND1) 5(GND2) 9(MNT1) 10(MNT2); U2 3(VDD+); U6 J1(NC1) J9(NC2) L1(NC3) L9(NC4); U7 4(XI) 9(SUSPEND) 10(WO_WLAN); U19 3(NC3) 4(NC4) 5(NC5) 6(NC6) 10(NC7) 11(NC8) 14(NC9) 15(NC10) 20(NC11) 21(NC12) 22(NC13) 26(NC17) 27(NC18) 28(NC19) 33(NC20) 35(NC22) 40(NC25) 45(NC26) 46(NC27) 47(NC28); U22 A4(NC_1) A6(NC_2) A9(NC_3) A11(NC_4) AA1(NC_122) AA2(NC_123) AA7(NC_124) AA8(NC_125) AA9(NC_126) AA10(NC_127) AA11(NC_128) AA12(NC_129) AA13(NC_130) AA14(NC_131) AE1(NC_132) AE14(NC_133) AG2(NC_134) AG13(NC_135) AH4(NC_136) AH6(NC_137) AH9(NC_138) AH11(NC_95) B2(NC_5) B13(NC_6) D1(NC_7) D14(NC_8) H1(NC_9) H2(NC_10) H6(NC_11) H7(NC_12) H8(NC_13) H9(NC_14) H10(NC_15) H11(NC_16) H12(NC_17) H13(NC_18) H14(NC_19) J1(NC_20) J7(NC_21) J8(NC_22) J9(NC_23) J10(NC_24) J11(NC_25) J12(NC_26) J13(NC_27) J14(NC_28) K1(NC_29) K3(NC_30) K5(NC_31) K7(NC_32) K8(NC_33) K9(NC_34) K10(NC_35) K11(NC_36) K12(NC_37) K13(NC_38) K14(NC_39) L1(NC_40) L2(NC_41) L3(NC_42) L4(A1) L12(NC_43) L13(NC_44) L14(NC_45) M1(NC_46) M2(NC_47) M3(NC_48) M5(NC_49) M8(NC_50) M9(NC_51) M10(NC_52) M12(NC_53) M13(NC_54) M14(NC_55) N1(NC_56) N2(NC_57) N3(NC_58) N10(NC_59) N12(NC_60) N13(NC_61) N14(NC_62) P1(NC_63) P2(NC_64) P3(NC_65) P10(NC_66) P12(NC_67) P13(NC_68) P14(NC_69) R1(NC_70) R2(NC_71) R3(NC_72) R5(NC_73) R12(NC_74) R13(NC_75) R14(NC_76) T1(NC_77) T2(NC_78) T3(NC_79) T5(NC_80) T12(NC_81) T13(NC_82) T14(NC_83) U1(NC_84) U2(NC_85) U3(NC_86) U6(NC_87) U7(NC_88) U10(NC_89) U12(NC_90) U13(NC_91) U14(NC_92) V1(NC_93) V2(NC_94) V3(NC_96) V12(NC_97) V13(NC_98) V14(NC_99) W1(NC_100) W2(NC_101) W3(NC_102) W7(NC_103) W8(NC_104) W9(NC_105) W10(NC_106) W11(NC_107) W12(NC_108) W13(NC_109) W14(NC_110) Y1(NC_111) Y3(NC_112) Y6(NC_113) Y7(NC_114) Y8(NC_115) Y9(NC_116) Y10(NC_117) Y11(NC_118) Y12(NC_119) Y13(NC_120) Y14(NC_121)

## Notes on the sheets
sheet 1
- HDMI TX
- ** HDMI Design guideline **
- A.routing
- The type and specification of the components  refer to the BOM
- 1.Route as 100 Ohm differential impedance.
- 2.Differential pairs should be routed on TOP layer only.
- 3.Differential pairs should be separated from other traces by GND .
- NA
- 2014-07-22
- B.trace length
- ECA NO
- DATE
- 1.The length for the differential pairs should be less than 5 inches.
- DESIGNED
- XIONGLIN 00282668
- 2.Match trace length of differential pairs, 5 mils max within a pair.
- HI3798MDMO1F_VERC
- 00001234
- C.component selection
- REVIEWED
- CHENYUZHU 149603
- 1.ESD components are suggested for ports protection.
- VER
- PART_NUMBER
- SHEET
- 18
- OF
- 18
- 2.All equivalent capacitance of ESD components should be < 0.8pF.
- A
- 03030001
- HUAWEI TECH CO.,LTD.
sheet 2
- VDAC OUTPUT
- The type and specification of the components  refer to the BOM
- NA
- 2014-07-22
- ECA NO
- DATE
- DESIGNED
- XIONGLIN 00282668
- HI3798MDMO1F_VERC
- 00001234
- REVIEWED
- CHENYUZHU 149603
- VER
- PART_NUMBER
- SHEET
- 17
- OF
- 18
- A
- 03030001
- HUAWEI TECH CO.,LTD.
- ** Design guideline **
- 1.All channel traces should be separated from other traces by GND.
- 2.ESD components are suggested for ports protection, default BAV99.
sheet 3
- FE PHY/UART
- Put C153 and C154 close to T2
- UART
- The type and specification of the components  refer to the BOM
- NA
- 2014-07-22
- ECA NO
- DATE
- DESIGNED
- XIONGLIN 00282668
- 00001234
- HI3798MDMO1F_VERC
- REVIEWED
- CHENYUZHU 149603
- VER
- PART_NUMBER
- SHEET
- 16
- OF
- 18
- A
- 03030001
- HUAWEI TECH CO.,LTD.
sheet 4
- Audio Output
- 1%
- 1%
- 1%
- 1%
- 1%
- The type and specification of the components  refer to the BOM
- NA
- 2014-07-22
- ECA NO
- DATE
- DESIGNED
- XIONGLIN 00282668
- HI3798MDMO1F_VERC
- 00001234
- REVIEWED
- CHENYUZHU 149603
- VER
- PART_NUMBER
- SHEET
- 15
- OF
- 18
- A
- 03030001
- HUAWEI TECH CO.,LTD.
sheet 5
- LED/IR
- LED
- IR
- H  Green
- L  Red
- The type and specification of the components  refer to the BOM
- NA
- 2014-07-22
- ECA NO
- DATE
- DESIGNED
- XIONGLIN 00282668
- HI3798MDMO1F_VERC
- 00001234
- REVIEWED
- CHENYUZHU 149603
- VER
- PART_NUMBER
- SHEET
- 14
- OF
- 18
- A
- 03030001
- HUAWEI TECH CO.,LTD.
sheet 6
- USB2.0/WIFI
- For Board Antenna
- ANTF:50ohm Resistance
- ETA6010:Current=1.3A
- USB0:usb_boot/adb
- For Board Antenna
- ANTF:50ohm Resistance
- The type and specification of the components  refer to the BOM
- NA
- 2014-07-22
- ECA NO
- DATE
- DESIGNED
- XIONGLIN 00282668
- HI3798MDMO1F_VERC
- 00001234
- REVIEWED
- CHENYUZHU 149603
- VER
- PART_NUMBER
- SHEET
- 13
- OF
- 18
- A
- 03030001
- HUAWEI TECH CO.,LTD.
sheet 7
- NAND FLASH/EMMC
- NAND FLASH/tSD
- eMMC/fSD
- fSD  10K
- NFWP
- 4GB
- 0:Protect
- H6 eMMC5.0
- 1:NOT Protect
- 4GB
- NAND FLASH
- C142=C143=100nF,C36=1uF,R215=4.7K,R57=0,C29=100uF,D1=diode,U19=nand
- others=NC,If use Micron nand flash,R57=NC
- eMMC
- Pay attention to pin38&pin39,these pins are NC for the MLC NAND of some
- C63=C123=C124=C93=C105=C323=C324=100nF,C100=2.2uF
- brands(such as Micron),but it should be connected to the VCC of
- others(such as Toshiba and Hynix).
- ,R203=R189=R12=R29=R58=R176=R177=R188=R202=47K,R212=10K,R86=0,U22=eMMC,others=NC
- Pls refer to the corresponding datasheet for detail.
- fSD
- T5 eMMC5.0
- C63=C123=C124=C93=C105=C323=C324=100nF,C100=2.2uF
- ,R203=R189=R12=R29=R58=R212=10K,R86=0,U22=fSD,others=NC
- R5 eMMC5.0
- The type and specification of the components  refer to the BOM
- NA
- 2014-07-22
- ECA NO
- DATE
- DESIGNED
- XIONGLIN 00282668
- HI3798MDMO1F_VERC
- 00001234
- REVIEWED
- CHENYUZHU 149603
- VER
- PART_NUMBER
- SHEET
- 12
- OF
- 18
- A
- 03030001
- HUAWEI TECH CO.,LTD.
sheet 8
- DDRB
- 1%
- 1%
- 1%
- 1%
- 1%
- 1%
- The type and specification of the components  refer to the BOM
- 1%
- NA
- 2014-07-22
- ECA NO
- DATE
- DESIGNED
- XIONGLIN 00282668
- 00001234
- HI3798MDMO1F_VERC
- REVIEWED
- CHENYUZHU 149603
- VER
- PART_NUMBER
- SHEET
- 11
- OF
- 18
- A
- 03030001
- HUAWEI TECH CO.,LTD.
